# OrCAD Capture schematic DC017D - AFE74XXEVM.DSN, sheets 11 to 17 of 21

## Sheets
11 SHEET 09 - RX INPUTS: size B; title: AFE INPUTS
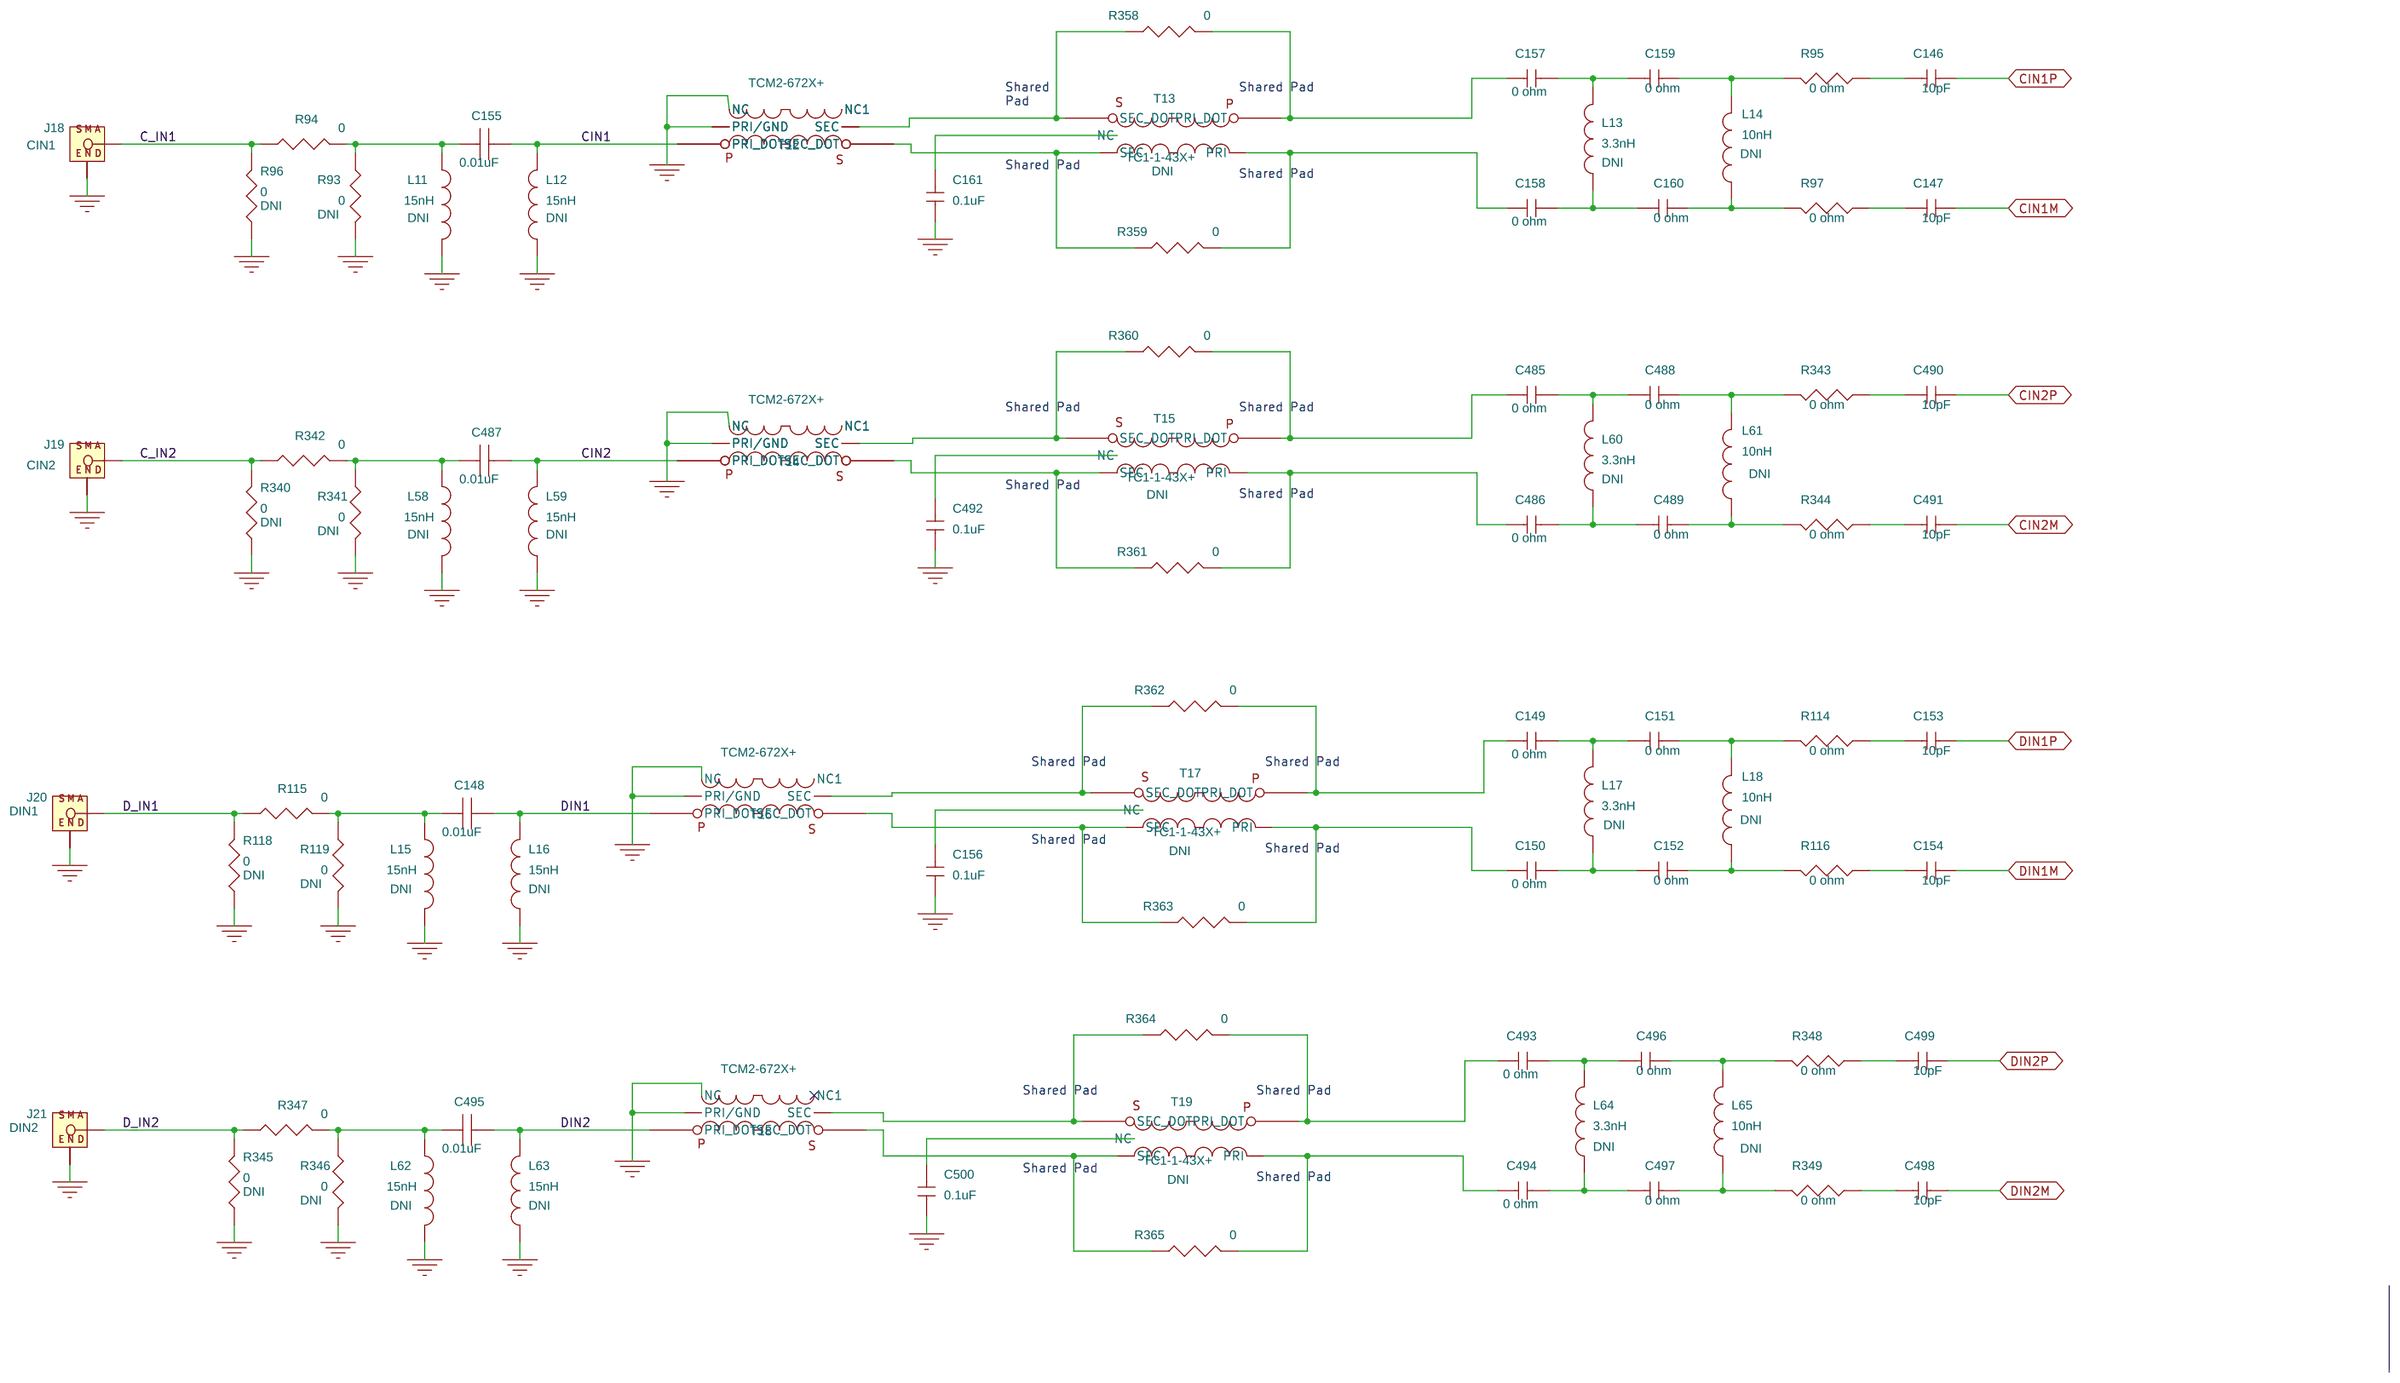
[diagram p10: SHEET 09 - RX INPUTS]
12 SHEET 10 - TX OUTPUTS: size B; title: AFE OUTPUTS
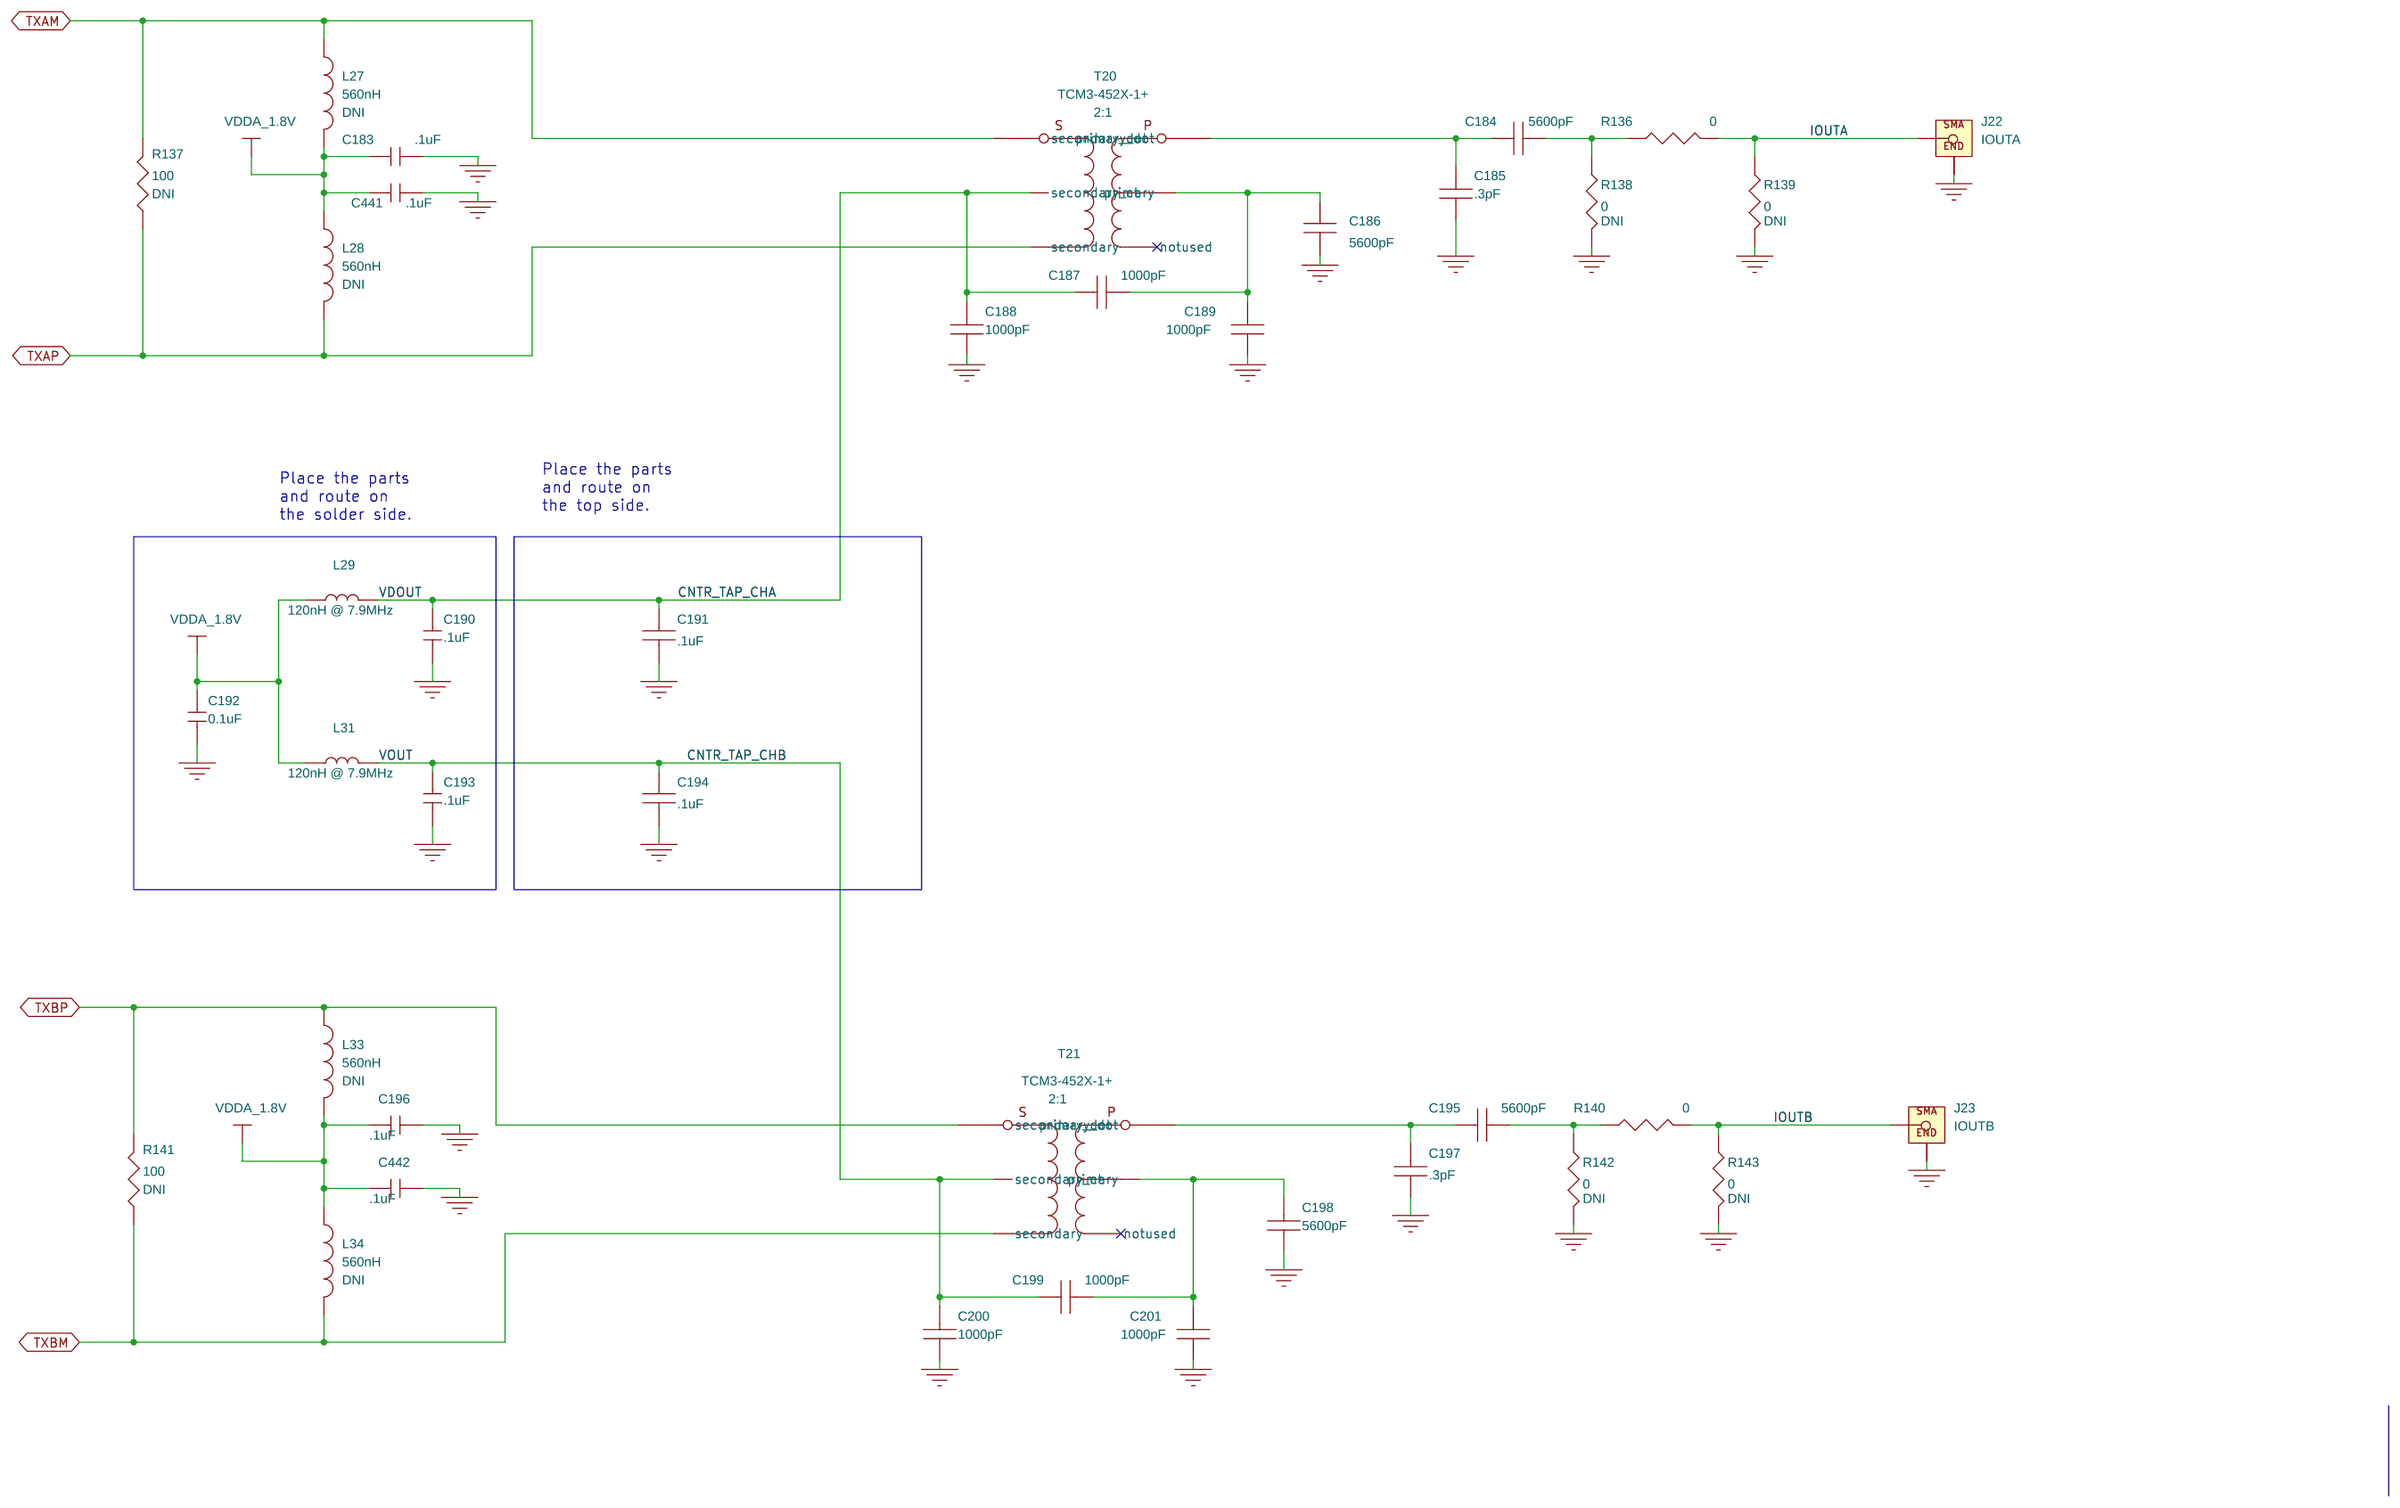
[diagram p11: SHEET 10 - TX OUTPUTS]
13 SHEET 11 - TX OUTPUTS: size B; title: AFE OUTPUTS
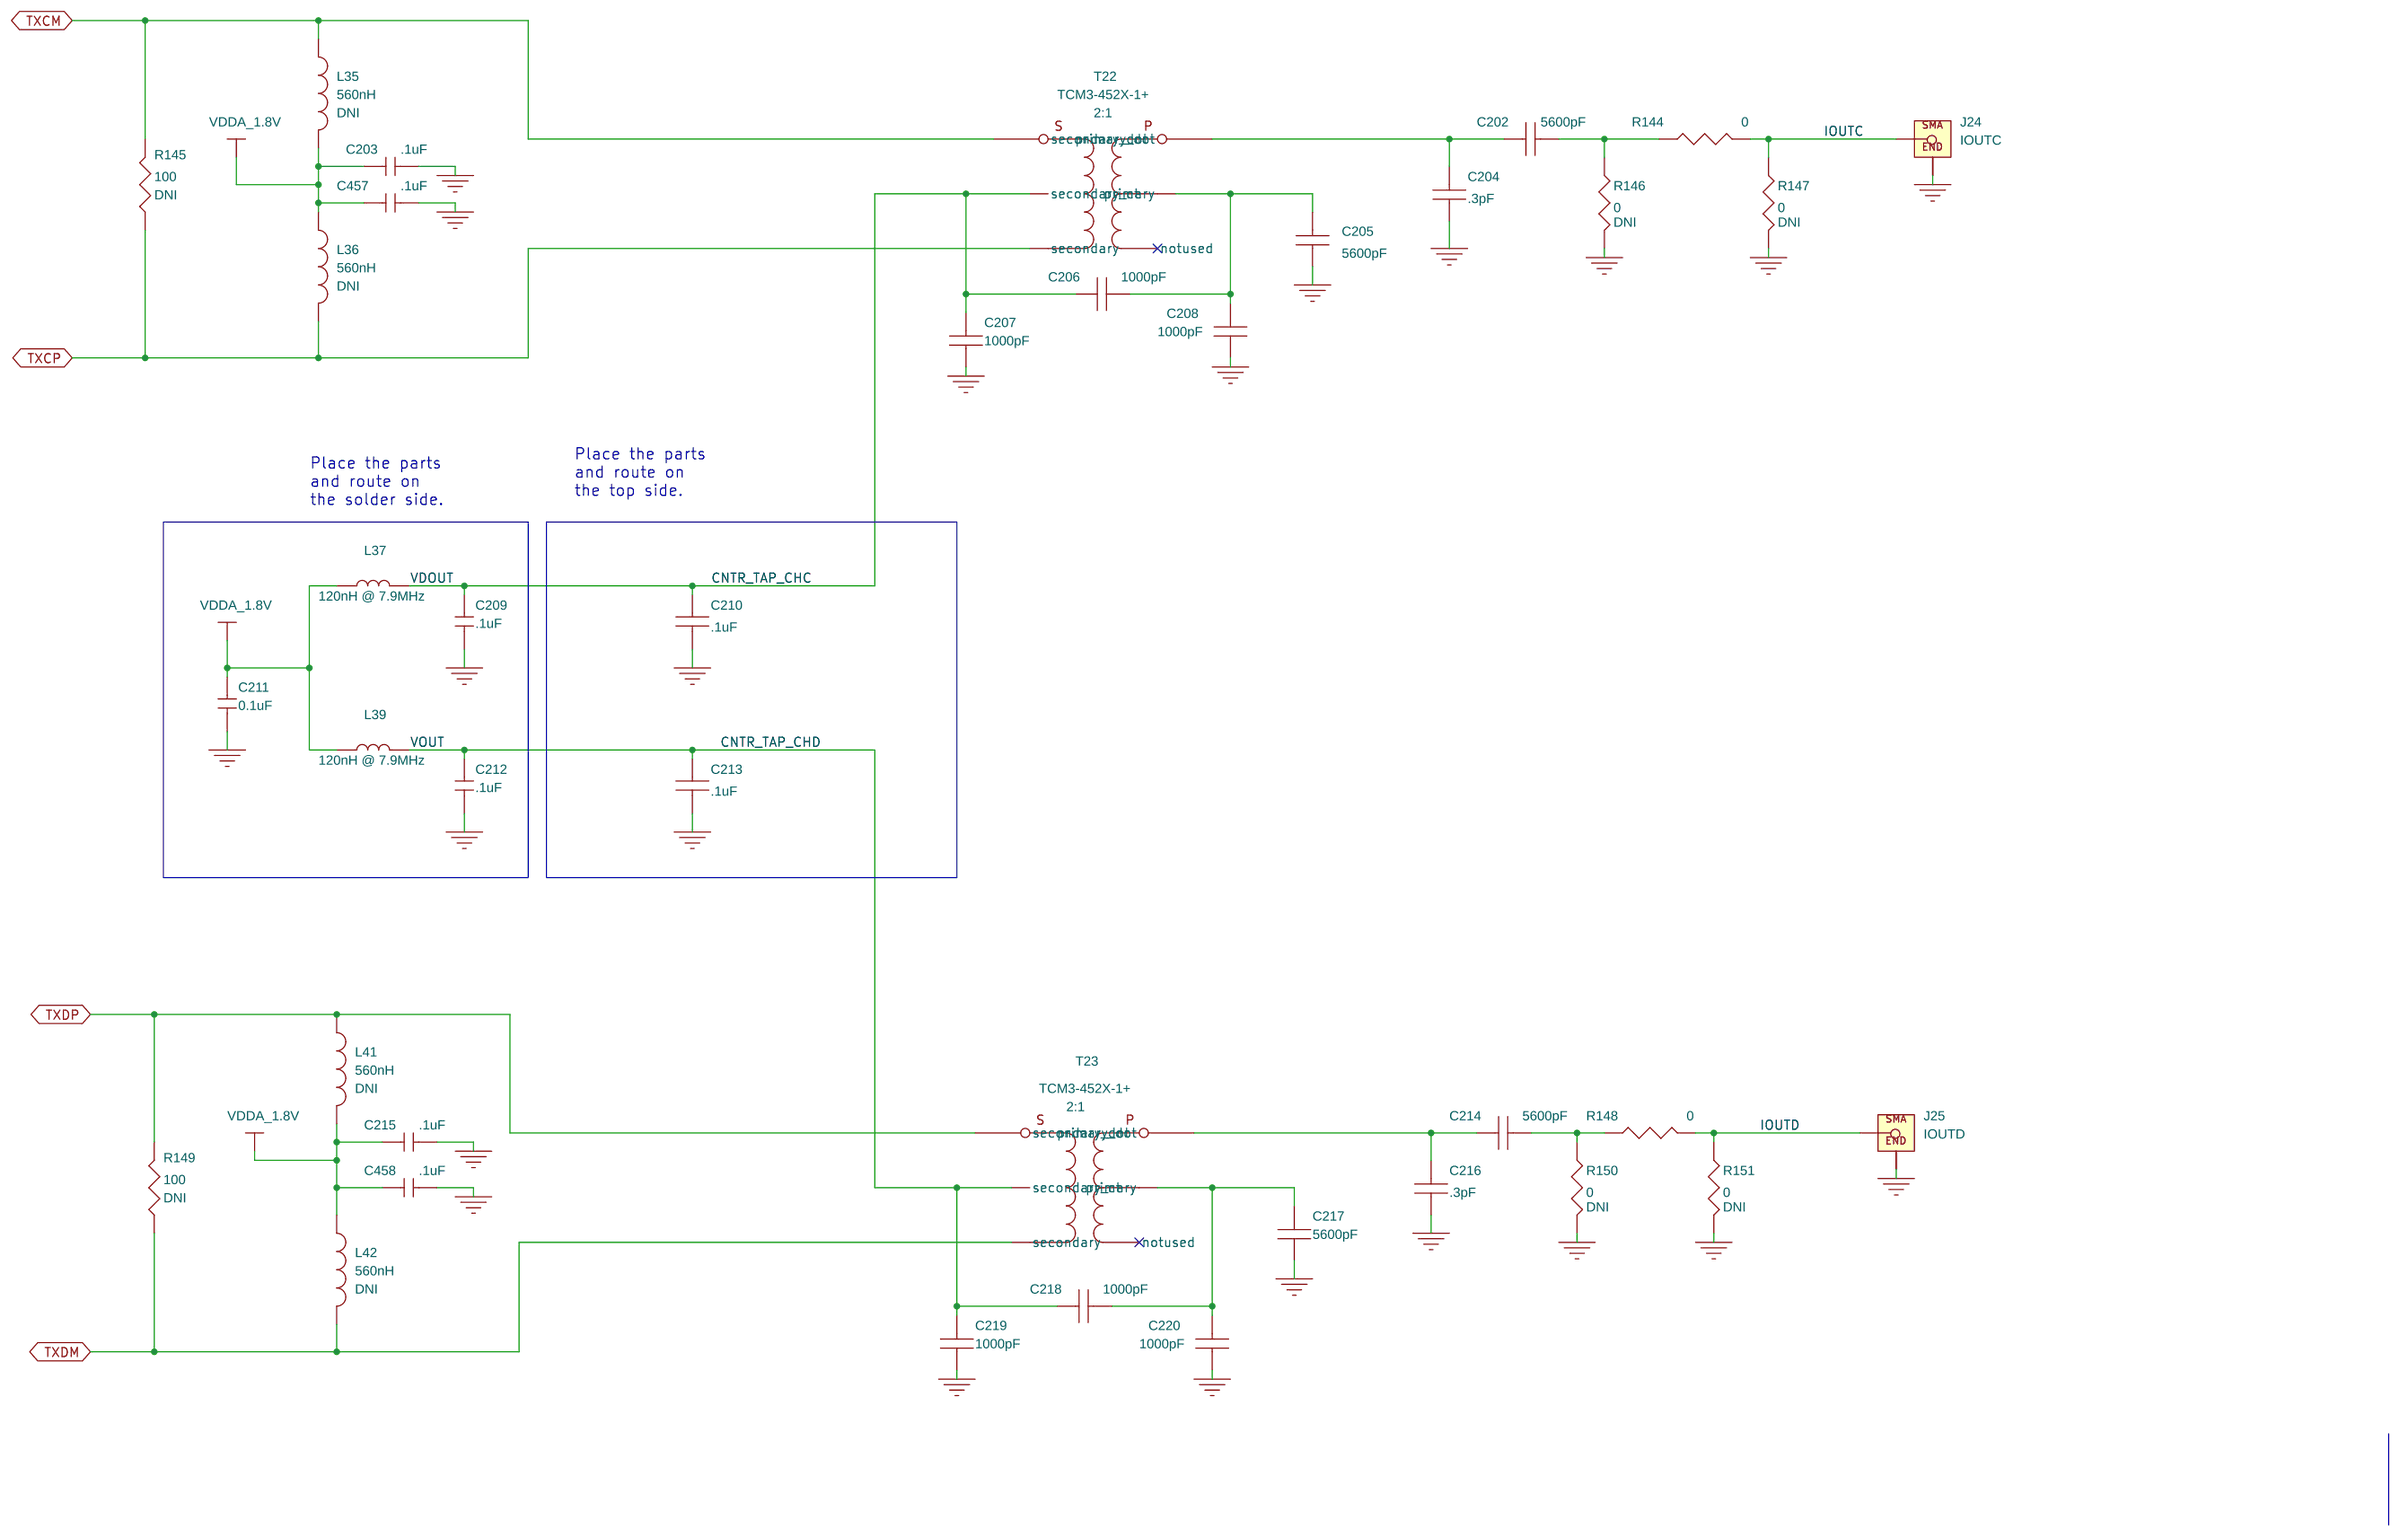
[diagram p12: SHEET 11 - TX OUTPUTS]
14 SHEET 12 - LMK INPUTS & OUTPUTS: size B; title: LMK
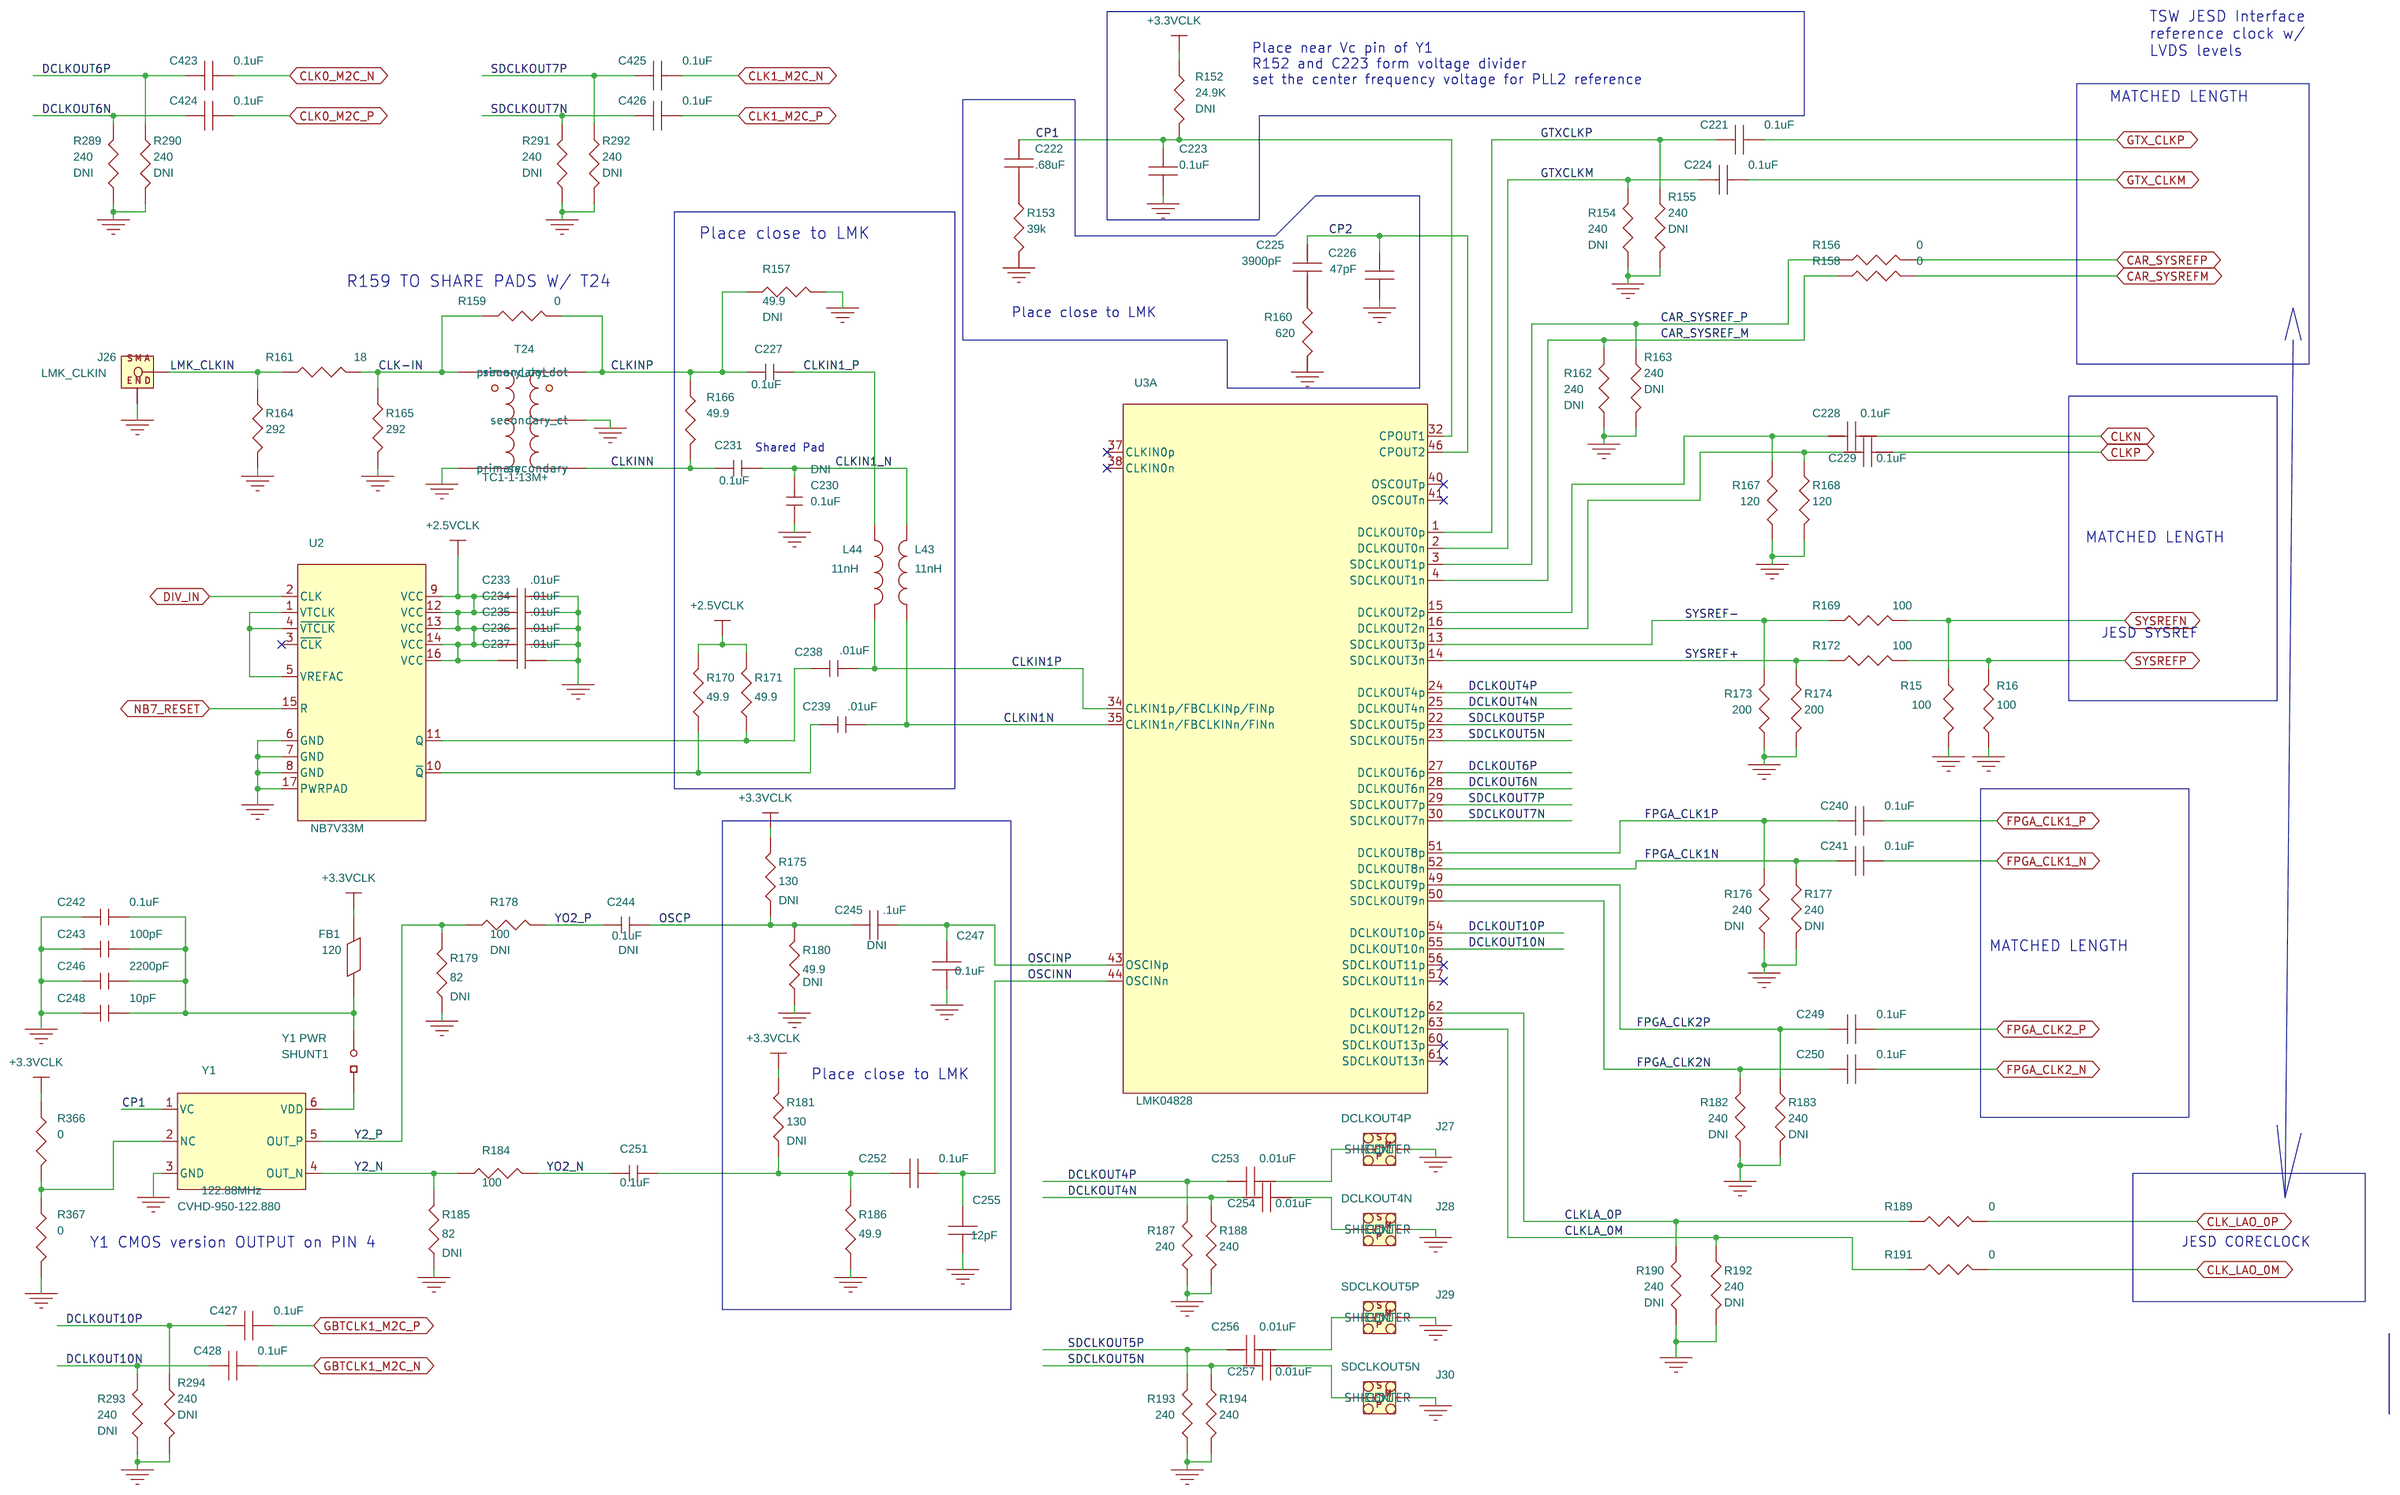
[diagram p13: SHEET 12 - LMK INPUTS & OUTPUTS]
15 SHEET 13 - LMK POWER & CONF: size B; title: LMK
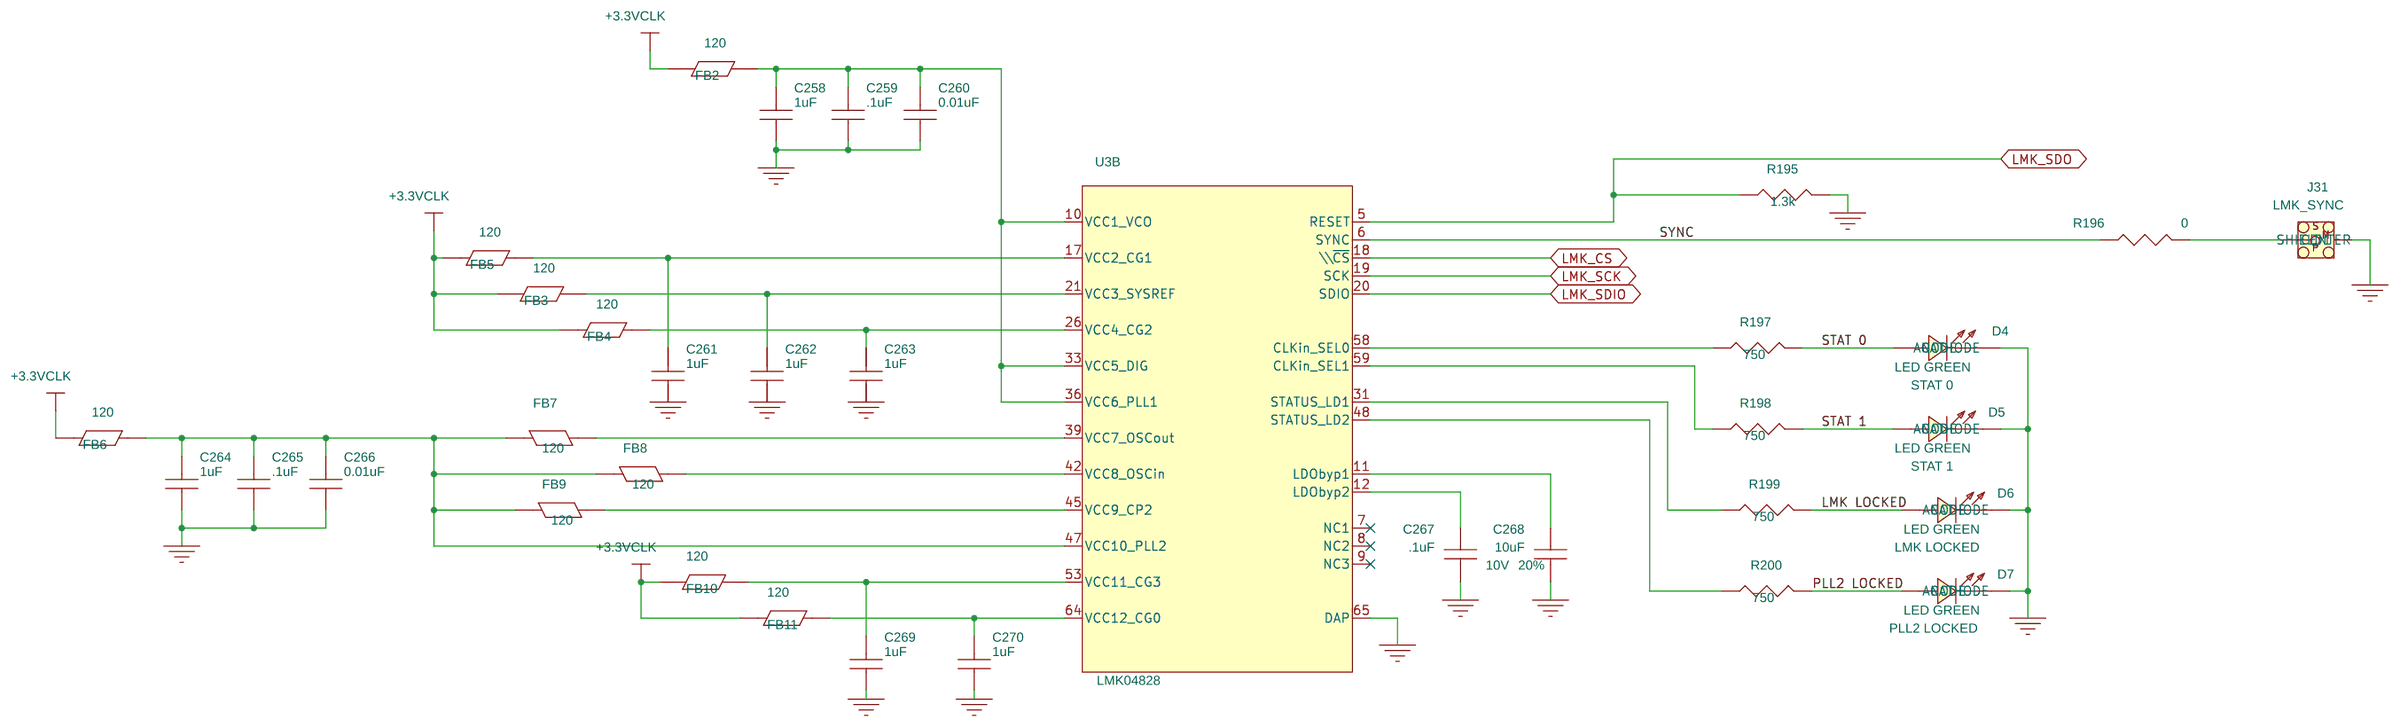
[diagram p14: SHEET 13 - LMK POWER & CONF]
16 SHEET 14 - FMC CONN: size B; title: FMC
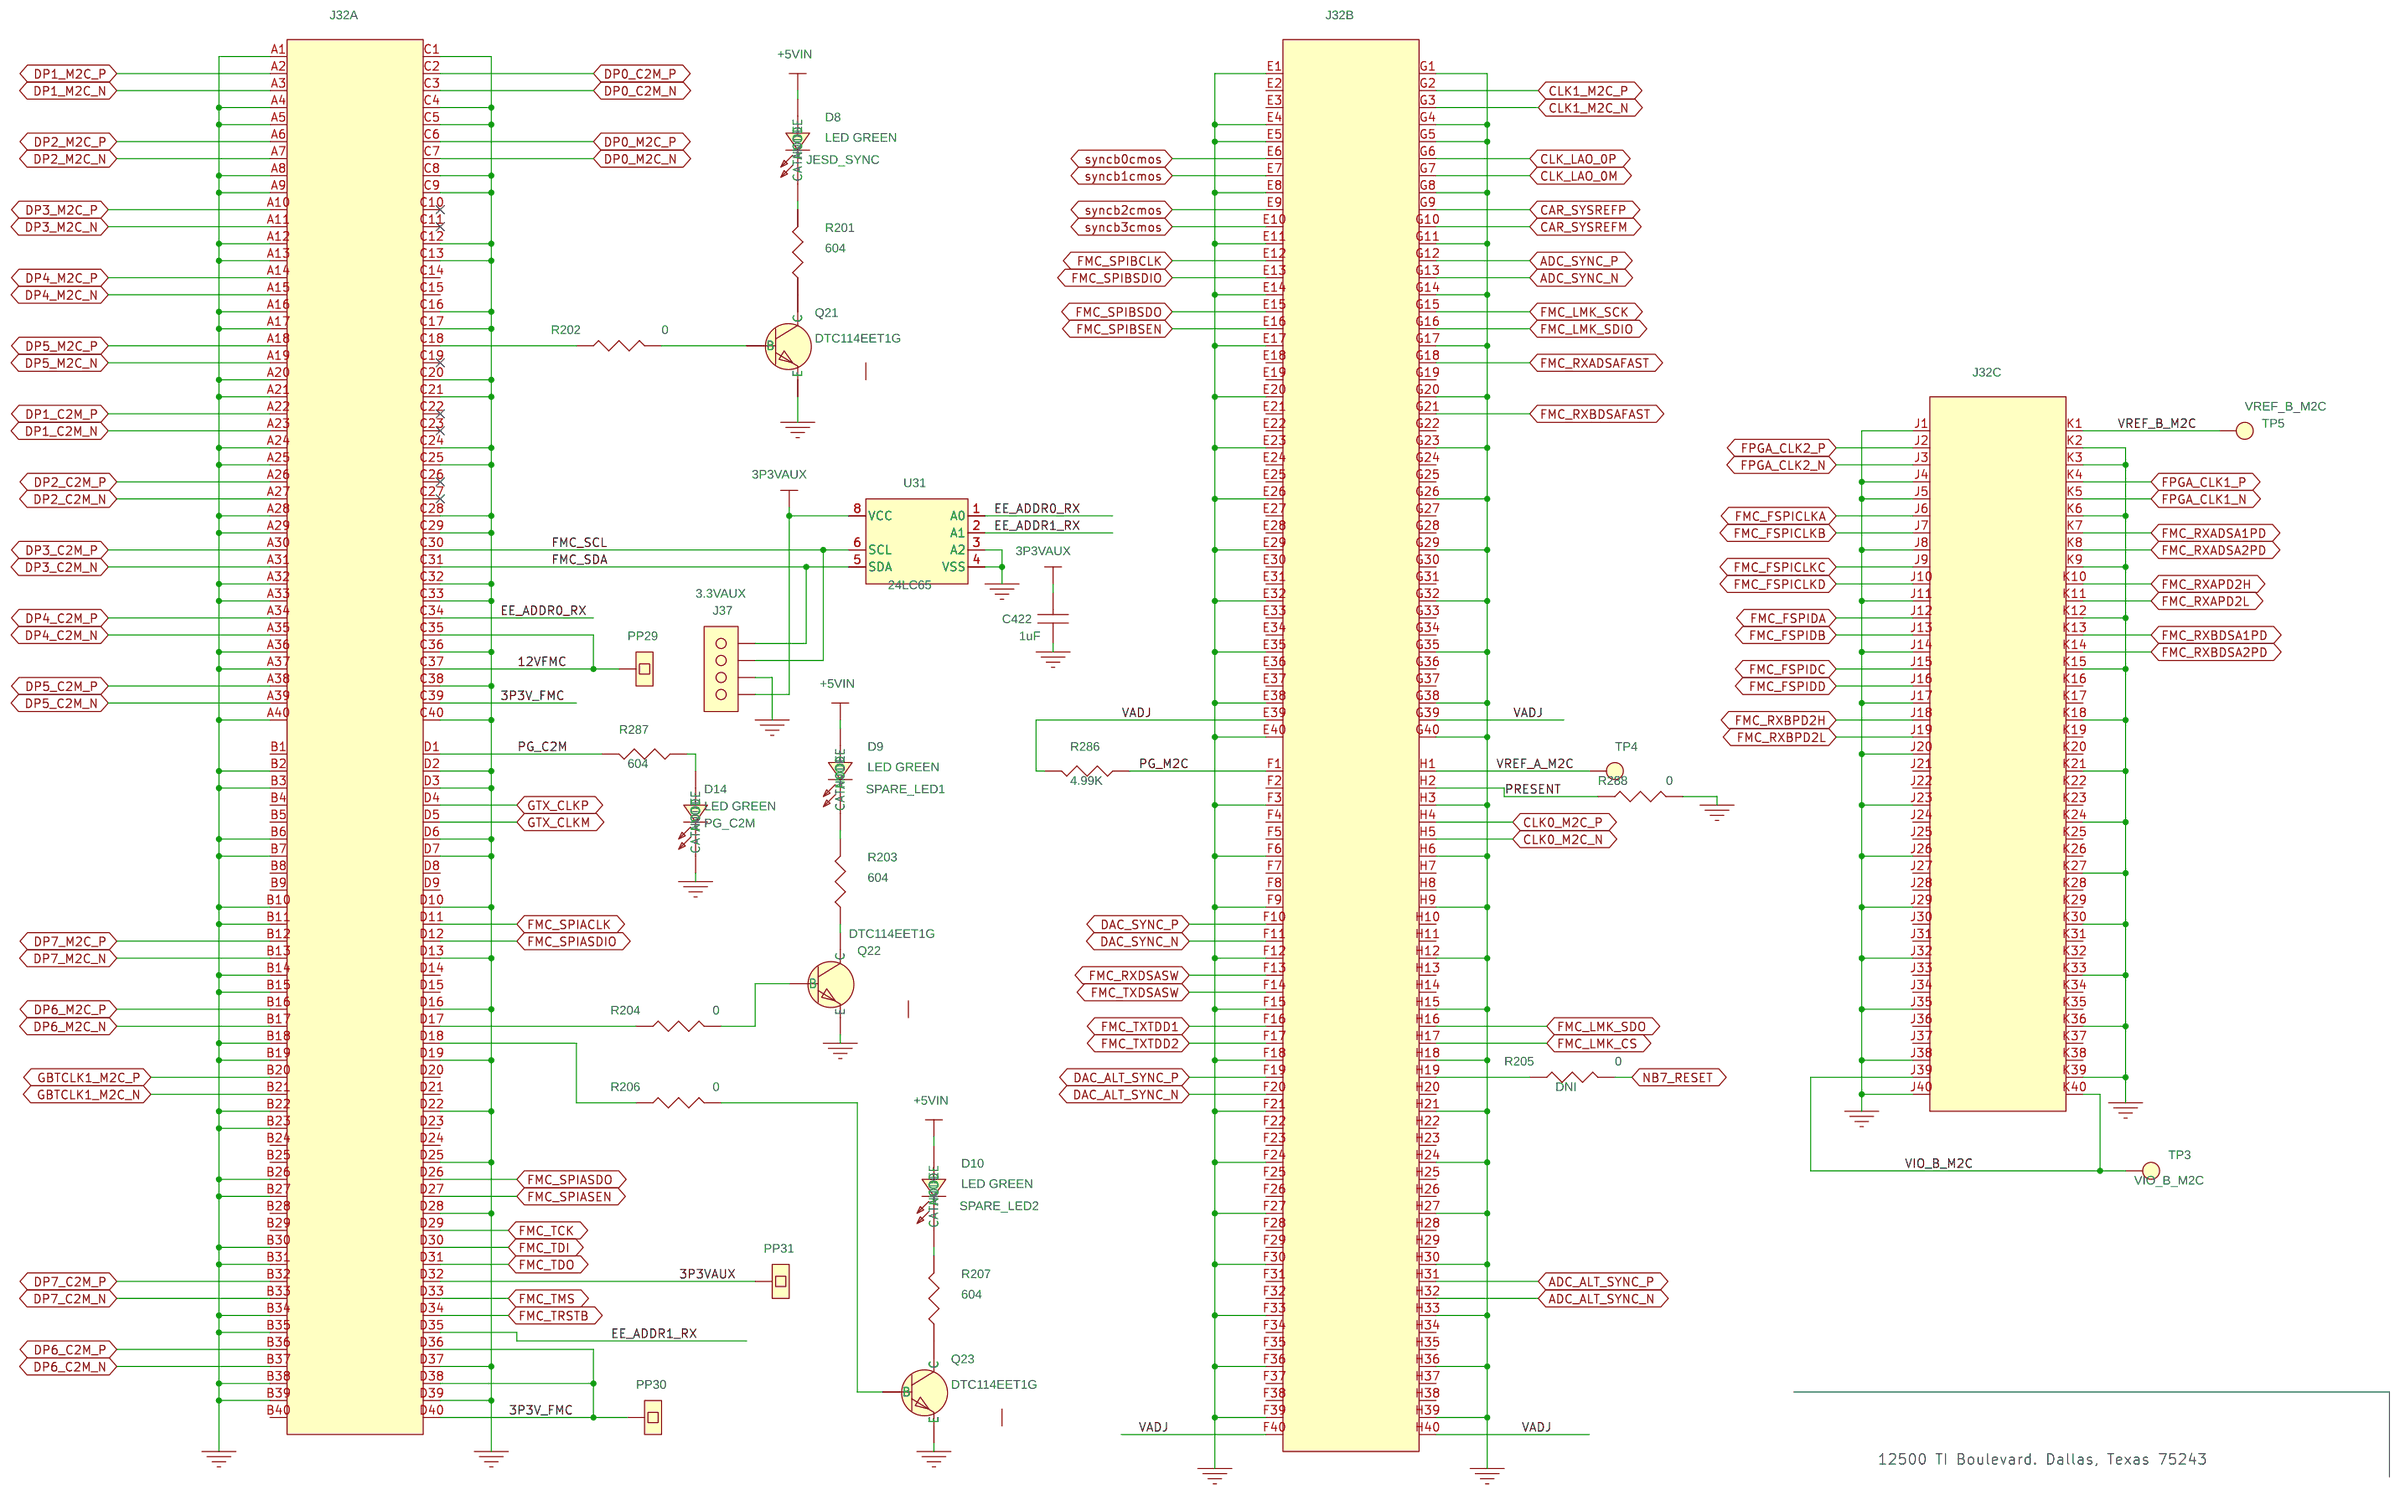
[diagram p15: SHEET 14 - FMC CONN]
17 SHEET 16 - POWER TREE: title: POWER TREE
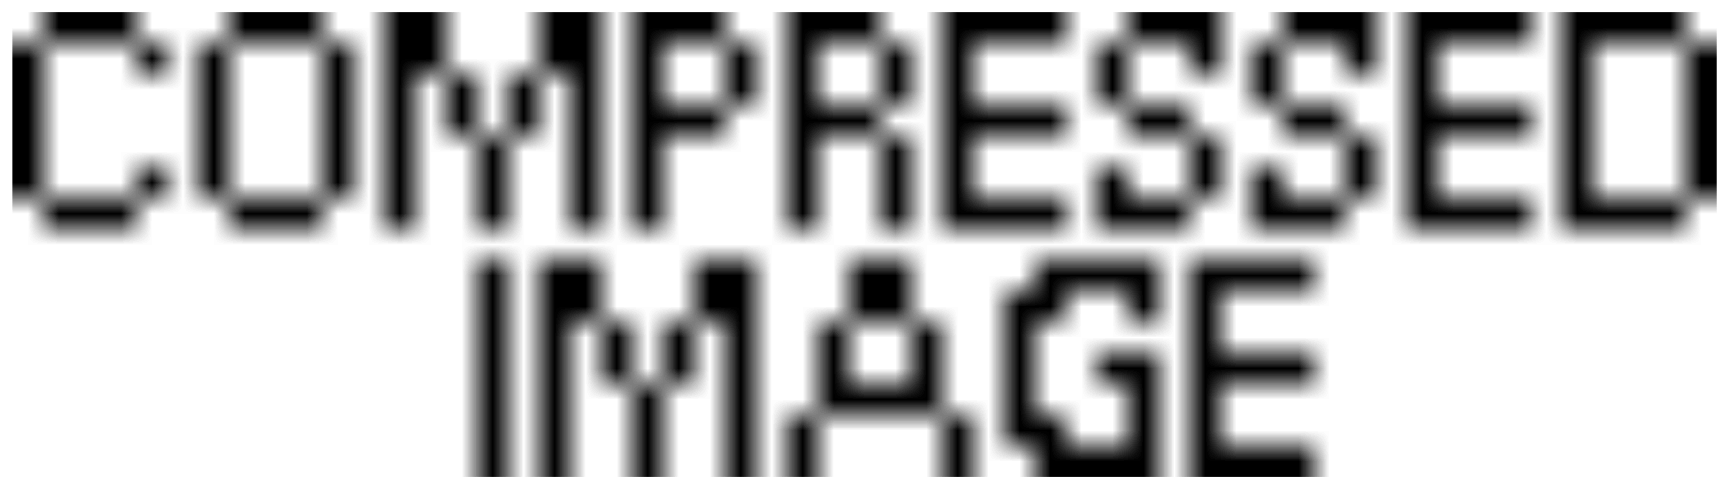
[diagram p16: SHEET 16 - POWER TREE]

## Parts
sheet SHEET 09 - RX INPUTS
C146  10pF  [0201]
C147  10pF  [0201]
C148  0.01uF  [0402]
C149  0 ohm  [0201]
C150  0 ohm  [0201]
C151  0 ohm  [0201]
C152  0 ohm  [0201]
C153  10pF  [0201]
C154  10pF  [0201]
C155  0.01uF  [0402]
C156  0.1uF  [0201]
C157  0 ohm  [0201]
C158  0 ohm  [0201]
C159  0 ohm  [0201]
C160  0 ohm  [0201]
C161  0.1uF  [0201]
C485  0 ohm  [0201]
C486  0 ohm  [0201]
C487  0.01uF  [0402]
C488  0 ohm  [0201]
C489  0 ohm  [0201]
C490  10pF  [0201]
C491  10pF  [0201]
C492  0.1uF  [0201]
C493  0 ohm  [0201]
C494  0 ohm  [0201]
C495  0.01uF  [0402]
C496  0 ohm  [0201]
C497  0 ohm  [0201]
C498  10pF  [0201]
C499  10pF  [0201]
C500  0.1uF  [0201]
J18  SMA, JACK, END LAUNCH  [SMA_SMEL_DUAL_PSF-S01_250x215]
J19  SMA, JACK, END LAUNCH  [SMA_SMEL_DUAL_PSF-S01_250x215]
J20  SMA, JACK, END LAUNCH  [SMA_SMEL_DUAL_PSF-S01_250x215]
J21  SMA, JACK, END LAUNCH  [SMA_SMEL_DUAL_PSF-S01_250x215]
L11  15nH  [0402]
L12  15nH  [0402]
L13  3.3nH  [0402]
L14  10nH  [0402]
L15  15nH  [0402]
L16  15nH  [0402]
L17  3.3nH  [0402]
L18  10nH  [0402]
L58  15nH  [0402]
L59  15nH  [0402]
L60  3.3nH  [0402]
L61  10nH  [0402]
L62  15nH  [0402]
L63  15nH  [0402]
L64  3.3nH  [0402]
L65  10nH  [0402]
R93  0  [0402]
R94  0  [0402]
R95  0 ohm  [0201]
R96  0  [0402]
R97  0 ohm  [0201]
R114  0 ohm  [0201]
R115  0  [0402]
R116  0 ohm  [0201]
R118  0  [0402]
R119  0  [0402]
R340  0  [0402]
R341  0  [0402]
R342  0  [0402]
R343  0 ohm  [0201]
R344  0 ohm  [0201]
R345  0  [0402]
R346  0  [0402]
R347  0  [0402]
R348  0 ohm  [0201]
R349  0 ohm  [0201]
R358  0  [0603]
R359  0  [0603]
R360  0  [0603]
R361  0  [0603]
R362  0  [0603]
R363  0  [0603]
R364  0  [0603]
R365  0  [0603]
T12  TCM2-672X+  [TFMR_6_160x150_50]
T13  TC1-1-43X+  [TFMR_5_150X150_50]
T14  TCM2-672X+  [TFMR_6_160x150_50]
T15  TC1-1-43X+  [TFMR_5_150X150_50]
T16  TCM2-672X+  [TFMR_6_160x150_50]
T17  TC1-1-43X+  [TFMR_5_150X150_50]
T18  TCM2-672X+  [TFMR_6_160x150_50]
T19  TC1-1-43X+  [TFMR_5_150X150_50]
sheet SHEET 10 - TX OUTPUTS
C183  .1uF  [0204]
C184  5600pF  [0402]
C185  .3pF  [0402]
C186  5600pF  [0402]
C187  1000pF  [0402]
C188  1000pF  [0402]
C189  1000pF  [0402]
C190  .1uF  [0402]
C191  .1uF  [0402]
C192  0.1uF  [0603]
C193  .1uF  [0402]
C194  .1uF  [0402]
C195  5600pF  [0402]
C196  .1uF  [0204]
C197  .3pF  [0402]
C198  5600pF  [0402]
C199  1000pF  [0402]
C200  1000pF  [0402]
C201  1000pF  [0402]
C441  .1uF  [0204]
C442  .1uF  [0204]
J22  SMA END LAUNCH  [SMA_SMEL_DUAL_PSF-S01_250x215]
J23  SMA END LAUNCH  [SMA_SMEL_DUAL_PSF-S01_250x215]
L27  560nH  [0402]
L28  560nH  [0402]
L29  120nH @ 7.9MHz  [IND_0603]
L31  120nH @ 7.9MHz  [IND_0603]
L33  560nH  [0402]
L34  560nH  [0402]
R136  0  [0402]
R137  100  [01005]
R138  0  [0402]
R139  0  [0402]
R140  0  [0402]
R141  100  [01005]
R142  0  [0402]
R143  0  [0402]
T20  TCM3-452X-1+  [TFMR_6_160x150_50]
T21  TCM3-452X-1+  [TFMR_6_160x150_50]
sheet SHEET 11 - TX OUTPUTS
C202  5600pF  [0402]
C203  .1uF  [0204]
C204  .3pF  [0402]
C205  5600pF  [0402]
C206  1000pF  [0402]
C207  1000pF  [0402]
C208  1000pF  [0402]
C209  .1uF  [0402]
C210  .1uF  [0402]
C211  0.1uF  [0603]
C212  .1uF  [0402]
C213  .1uF  [0402]
C214  5600pF  [0402]
C215  .1uF  [0204]
C216  .3pF  [0402]
C217  5600pF  [0402]
C218  1000pF  [0402]
C219  1000pF  [0402]
C220  1000pF  [0402]
C457  .1uF  [0204]
C458  .1uF  [0204]
J24  SMA END LAUNCH  [SMA_SMEL_DUAL_PSF-S01_250x215]
J25  SMA END LAUNCH  [SMA_SMEL_DUAL_PSF-S01_250x215]
L35  560nH  [0402]
L36  560nH  [0402]
L37  120nH @ 7.9MHz  [IND_0603]
L39  120nH @ 7.9MHz  [IND_0603]
L41  560nH  [0402]
L42  560nH  [0402]
R144  0  [0402]
R145  100  [01005]
R146  0  [0402]
R147  0  [0402]
R148  0  [0402]
R149  100  [01005]
R150  0  [0402]
R151  0  [0402]
T22  TCM3-452X-1+  [TFMR_6_160x150_50]
T23  TCM3-452X-1+  [TFMR_6_160x150_50]
sheet SHEET 12 - LMK INPUTS & OUTPUTS
C221  0.1uF  [0201]
C222  .68uF  [0402]
C223  0.1uF  [0201]
C224  0.1uF  [0201]
C225  3900pF  [0201]
C226  47pF  [0201]
C227  0.1uF  [0201]
C228  0.1uF  [0201]
C229  0.1uF  [0201]
C230  0.1uF  [0201]
C231  0.1uF  [0201]
C233  .01uF  [0201]
C234  .01uF  [0201]
C235  .01uF  [0201]
C236  .01uF  [0201]
C237  .01uF  [0201]
C238  .01uF  [0201]
C239  .01uF  [0201]
C240  0.1uF  [0201]
C241  0.1uF  [0201]
C242  0.1uF  [0201]
C243  100pF  [0201]
C244  0.1uF  [0201]
C245  .1uF  [0201]
C246  2200pF  [0201]
C247  0.1uF  [0201]
C248  10pF  [0201]
C249  0.1uF  [0201]
C250  0.1uF  [0201]
C251  0.1uF  [0201]
C252  0.1uF  [0201]
C253  0.01uF  [0201]
C254  0.01uF  [0201]
C255  12pF  [0201]
C256  0.01uF  [0201]
C257  0.01uF  [0201]
C423  0.1uF  [0201]
C424  0.1uF  [0201]
C425  0.1uF  [0201]
C426  0.1uF  [0201]
C427  0.1uF  [0201]
C428  0.1uF  [0201]
FB1  120  [0402]
J26  SMA, JACK, END LAUNCH  [SMA_SMEL_DUAL_PSF-S01_250x215]
J27  SMP CONN  [smp_b120]
J28  SMP CONN  [smp_b120]
J29  SMP CONN  [smp_b120]
J30  SMP CONN  [smp_b120]
L43  11nH  [0402]
L44  11nH  [0402]
R15  100  [0201]
R16  100  [0201]
R152  24.9K  [0201]
R153  39k  [0201]
R154  240  [0201]
R155  240  [0201]
R156  0  [0201]
R157  49.9  [0201]
R158  0  [0201]
R159  0  [0603]
R160  620  [0201]
R161  18  [0402]
R162  240  [0201]
R163  240  [0201]
R164  292  [0402]
R165  292  [0402]
R166  49.9  [0402]
R167  120  [0201]
R168  120  [0201]
R169  100  [0201]
R170  49.9  [0201]
R171  49.9  [0201]
R172  100  [0201]
R173  200  [0201]
R174  200  [0201]
R175  130  [0201]
R176  240  [0201]
R177  240  [0201]
R178  100  [0201]
R179  82  [0201]
R180  49.9  [0201]
R181  130  [0201]
R182  240  [0201]
R183  240  [0201]
R184  100  [0201]
R185  82  [0201]
R186  49.9  [0201]
R187  240  [0201]
R188  240  [0201]
R189  0  [0201]
R190  240  [0201]
R191  0  [0201]
R192  240  [0201]
R193  240  [0201]
R194  240  [0201]
R289  240  [0201]
R290  240  [0201]
R291  240  [0201]
R292  240  [0201]
R293  240  [0201]
R294  240  [0201]
R366  0  [0402]
R367  0  [0402]
SHUNT1  SHUNT JUMPER  [HDR_THVT_1x2_100_M]
T24  TC1-1-13M+  [TFMR_5_150x150_50]
U2  NB7V33M  [qfn_16_124x124_pwrpad]
Y1  122.88MHz  [VCXO_6_CUSTOM]
sheet SHEET 13 - LMK POWER & CONF
C258  1uF  [0402]
C259  .1uF  [0201]
C260  0.01uF  [0201]
C261  1uF  [0402]
C262  1uF  [0402]
C263  1uF  [0402]
C264  1uF  [0402]
C265  .1uF  [0201]
C266  0.01uF  [0201]
C267  .1uF  [0201]
C268  10uF  [0402]
C269  1uF  [0402]
C270  1uF  [0402]
D4  LED GREEN  [LED_0603]
D5  LED GREEN  [LED_0603]
D6  LED GREEN  [LED_0603]
D7  LED GREEN  [LED_0603]
FB2  120  [0402]
FB3  120  [0402]
FB4  120  [0402]
FB5  120  [0402]
FB6  120  [0402]
FB7  120  [0402]
FB8  120  [0402]
FB9  120  [0402]
FB10  120  [0402]
FB11  120  [0402]
J31  SMP CONN  [smp_b120]
R195  1.3k  [0201]
R196  0  [0402]
R197  750  [0402]
R198  750  [0402]
R199  750  [0402]
R200  750  [0402]
U3  LMK04828  [QFN_64_360X360_0P50MM_PWRPAD]  (sections A,B)
sheet SHEET 14 - FMC CONN
C422  1uF  [0402]
D8  LED GREEN  [LED_0603]
D9  LED GREEN  [LED_0603]
D10  LED GREEN  [LED_0603]
D14  LED GREEN  [LED_0603]
J32  CON_SMVT_40x10_SEAM  [CON_SMVT_40X10_SEAM_MTG]  (sections A,B,C)
J37  HDR, THVT, 4POS, .100, GOLD  [HDR_THVT_1x4_100_M]
PP29  PROBE POINT  [PROBE_POINT_22PAD]
PP30  PROBE POINT  [PROBE_POINT_22PAD]
PP31  PROBE POINT  [PROBE_POINT_22PAD]
Q21  DTC114EET1G  [SOT_416_3_63x31]
Q22  DTC114EET1G  [SOT_416_3_63x31]
Q23  DTC114EET1G  [SOT_416_3_63x31]
R201  604  [0402]
R202  0  [0402]
R203  604  [0402]
R204  0  [0402]
R205  0  [0402]
R206  0  [0402]
R207  604  [0402]
R286  4.99K  [0402]
R287  604  [0402]
R288  0  [0402]
TP3  TP_THVT_060_RND-WHT  [TP_THVT_060_RND]
TP4  TP_THVT_060_RND-WHT  [TP_THVT_060_RND]
TP5  TP_THVT_060_RND-WHT  [TP_THVT_060_RND]
U31  24LC65  [SO_8_210X212_50]

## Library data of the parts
C146 C147 C153 C154 C490 C491 C498 C499 = CAP_0603_0.1uF_H: Mfr_Name: Murata; Mfr_Part_Number: GJM0336C1E100GB01D; TOL: 2%; Voltage: 25V
C148 C155 C487 C495 = CAP_NP_1: Mfr_Name: MURATA; Mfr_Part_Number: GCM155R71H103KA55J; TOL: 10%; VOLTAGE: 50V
C149 C150 C157 C158 C485 C486 C493 C494 = CAP_0402_0.01uF_H: Mfr_Name: Panasonic; Mfr_Part_Number: ERJ-1GN0R00C
C151 C152 C159 C160 C488 C489 C496 C497 = CAP_0603_0.1uF_H: Mfr_Name: Panasonic; Mfr_Part_Number: ERJ-1GN0R00C
C156 C161 C227 C231 C492 C500 = CAP_0402_0.01uF_H: Mfr_Name: TDK; Mfr_Part_Number: C0603X7S1A104K030BC; TOL: 10%; VOLTAGE: 10V
J18 = SMA-END_PLUG_ROUND_0: Mfr_Name: Johnson Components; Mfr_Part_Number: 142-0711-821; TI_Silktext: CIN1
J19 = SMA-END_PLUG_ROUND_0: Mfr_Name: Johnson Components; Mfr_Part_Number: 142-0711-821; TI_Silktext: CIN2
J20 = SMA-END_PLUG_ROUND_0: Mfr_Name: Johnson Components; Mfr_Part_Number: 142-0711-821; TI_Silktext: DIN1
J21 = SMA-END_PLUG_ROUND_0: Mfr_Name: Johnson Components; Mfr_Part_Number: 142-0711-821; TI_Silktext: DIN2
L11 L12 L15 L16 L58 L59 L62 L63 = CHOKE: Mfr_Name: Coilcraft; Mfr_Part_Number: 0402HP-15NXGLU; Note: DNI
L13 L17 L60 L64 = CHOKE: Mfr_Name: Coilcraft; Mfr_Part_Number: 0402HP-3N3XGLU; Note: DNI
L14 L18 L61 L65 = CHOKE: Mfr_Name: Coilcraft; Mfr_Part_Number: 0402HP-10NXGLU; Note: DNI
R93 R96 R118 R119 R205 R340 R341 R345 R346 = Res_0603_Zero_H: Mfr_Part_Number: ERJ-2GE0R00X; Note: DNI
R94 R115 R202 R204 R206 R288 R342 R347 = Res_0603_Zero_H: Mfr_Part_Number: ERJ-2GE0R00X
R95 R97 R114 R116 R343 R344 R348 R349 = Res_0402_Zero_H_DNI: Mfr_Name: Panasonic; Mfr_Part_Number: ERJ-1GN0R00C
R159 R358-R365 = Res_0603_Zero_DNI: Mfr_Part_Number: ERJ-3GEY0R00V
T12 T14 T16 T18 = BALUN_TCM2-672X+: Mfr_Part_Number: TCM2-672X-1+
T13 T15 T17 T19 = BALUN_TC1-1-43X+: Mfr_Part_Number: TC1-1-43X-2+; Note: DNI
C183 C196 C203 C215 C441 C442 C457 C458 = CAP0402_0: Mfr_Name: Murata; Mfr_Part_Number: LLL153C80J104ME01E; TOL: 20%; Voltage: 6.3V
C184 C186 C195 C198 C202 C205 C214 C217 = CAPACITOR_NP_1: Mfr_Name: Yageo; Mfr_Part_Number: CC0402KRX7R7BB562; TOL: 10%; Voltage: 16V
C185 C197 C204 C216 = CAPACITOR_NP_1: Mfr_Name: MURATA; Mfr_Part_Number: GRM1555C1HR30WA01D; TOL: .05pF; Voltage: 50V
C187-C189 C199-C201 C206-C208 C218-C220 = CAPACITOR_NP_1: Mfr_Name: Samsung; Mfr_Part_Number: CL05B102KO5NNNC; TOL: 10%; Voltage: 16V
C190 C193 C209 C212 = CAP_0603_0.1uF: Mfr_Name: MURATA; Mfr_Part_Number: GCM155R71C104KA55D; Voltage: 16V
C191 C194 C210 C213 = CAPACITOR_NP_1: Mfr_Name: MURATA; Mfr_Part_Number: GCM155R71C104KA55D; TOL: 10%; Voltage: 16V
C192 C211 = CAP_0603_0.1uF
J22 = TMP_0: Mfr_Name: Johnson Components; Mfr_Part_Number: 142-0711-841; TI_Silktext: IOUTA
J23 = TMP_0: Mfr_Name: Johnson Components; Mfr_Part_Number: 142-0711-841; TI_Silktext: IOUTB
L27 L28 L33-L36 L41 L42 = CHOKE: Mfr_Name: Coilcraft; Mfr_Part_Number: 0402AF-561XJLU; Note: DNI
L29 L31 L37 L39 = IND_0603_120nH_H: Mfr_Name: COILCRAFT; Mfr_Part_Number: 0603AF-121XJRU
R136 R140 R144 R148 = Res_0402_10_H: Mfr_Part_Number: ERJ-2GE0R00X
R137 R141 R145 R149 = Res_0402_100_H: Mfr_Part_Number: ERJ-XGNJ101Y; Note: DNI
R138 R139 R142 R143 R146 R147 R150 R151 = R: Mfr_Name: PANASONIC; Mfr_Part_Number: ERJ-2GE0R00X; Note: DNI; TOL: 5%
T20-T23 = TFMR_6_TCM3-452X+: Impedance Ratio: 2:1; Mfr_Part_Number: TCM2-452X-2+
J24 = TMP_0: Mfr_Name: Johnson Components; Mfr_Part_Number: 142-0711-841; TI_Silktext: IOUTC
J25 = TMP_0: Mfr_Name: Johnson Components; Mfr_Part_Number: 142-0711-841; TI_Silktext: IOUTD
C221 C224 C240 C241 C247 C249 C250 C423-C428 = CAPACITOR_NP_1: Mfr_Name: MURATA; Mfr_Part_Number: GRM033R61A104KE15D; TOL: 10%; Voltage: 16V
C222 = CAP_NP_0: Mfr_Name: TDK; Mfr_Part_Number: C1005X7S0J684K050BC; TOL: 10%; VOLTAGE: 6.3V
C223 C252 = CAP_NP_0: Mfr_Name: MURATA; Mfr_Part_Number: GRM033R61A104KE15D; TOL: 10%; VOLTAGE: 16V
C225 = CAP_NP_0: Mfr_Name: AVX; Mfr_Part_Number: 0201ZD392KAT2A; TOL: 10%; VOLTAGE: 10V
C226 = CAP_NP_0: Mfr_Name: MURATA; Mfr_Part_Number: GRM0335C1E470JA01D; TOL: 5%; VOLTAGE: 25V
C228 C229 = CAP_NP_1: Mfr_Name: MURATA; Mfr_Part_Number: GRM033R61A104KE15D; TOL: 10%; VOLTAGE: 16V
C230 = CAP_0402_0.1uF: Mfr_Name: MURATA; Mfr_Part_Number: GRM033R61A104KE15D; Note: DNI; TOL: 10%; VOLTAGE: 16V
C233-C239 = CAP_0402_0.01uF_H: Mfr_Part_Number: GRM033R71A103KA01D; TOL: 10%; VOLTAGE: 10V
C242 C251 = CAP_0402_0.1uF_H: Mfr_Part_Number: GRM033R61A104KE15D; TOL: 10%; Voltage: 16V
C243 = CAP_0603_100pF_H: Mfr_Name: Murata; Mfr_Part_Number: GRM033R71E101KA01D
C244 = CAP_0402_0.1uF_H: Mfr_Part_Number: GRM033R61A104KE15D; Note: DNI; TOL: 10%; Voltage: 16V
C245 = CAP_NP_0: Mfr_Name: MURATA; Mfr_Part_Number: GRM033R61A104KE15D; Note: DNI; TOL: 10%; VOLTAGE: 16V
C246 = CAP_0402_2200pF_H: Mfr_Part_Number: GRM033R71C222KA88D
C248 = CAP_0402_10pF_H: Mfr_Part_Number: GJM0336C1E100GB01D
C253 C254 C256 C257 = CAP_NP_1: Mfr_Name: MURATA; Mfr_Part_Number: GRM033R71A103KA01D; TOL: 10%; VOLTAGE: 10V
C255 = CAPACITOR_NP_1: Mfr_Name: Kemet; Mfr_Part_Number: CBR02C120F3GAC; TOL: 1%; Voltage: 25V
FB1-FB11 = FERRITE_BEAD_0402_H: Isat: 500mA; Mfr_Name: Taiyo Yuden; Mfr_Part_Number: BKP1005HS121-T
J26 = SMA-END_PLUG_ROUND_0: Mfr_Name: Johnson Components; Mfr_Part_Number: 142-0711-821; TI_Silktext: LMK_CLKIN
J27 = SMP_PLUG_SMT: TI_Silktext: DCLKOUT4P
J28 = SMP_PLUG_SMT: TI_Silktext: DCLKOUT4N
J29 = SMP_PLUG_SMT: TI_Silktext: SDCLKOUT5P
J30 = SMP_PLUG_SMT: TI_Silktext: SDCLKOUT5N
L43 L44 = CHOKE: Mfr_Name: Coilcraft; Mfr_Part_Number: 0402HP-11NXGLU
R15 R16 R169 R172 = Res_0402_Zero_H_DNI: Mfr_Part_Number: ERJ-1GNJ101C
R152 = Res_0402_24.9: Mfr_Part_Number: ERJ-1GNF2492C; Note: DNI
R153 = R_1: CLASS: DISCRETE; Mfr_Name: PANASONIC; Mfr_Part_Number: ERJ-1GNF3902C; TOL: 1%
R154 R155 R162 R163 R176 R177 R182 R183 R190 R192 R289-R294 = Res_0402_249: Mfr_Part_Number: ERJ-U01F2400C; Note: DNI
R156 R158 R189 R191 = Res_0402_Zero_H_DNI: Mfr_Part_Number: ERJ-1GN0R00C
R157 = Res_0402_49.9: Mfr_Name: VISHAY DALE; Mfr_Part_Number: CRCW020149R9FKED; Note: DNI; TOL: 1%; Wattage: 1/20W
R160 = R_1: CLASS: DISCRETE; Mfr_Name: PANASONIC; Mfr_Part_Number: ERJ-1GNJ621C; TOL: 1%
R161 = Res_0402_18: Mfr_Part_Number: ERJ-2RKF18R0X
R164 R165 = Res_0402_270: Mfr_Part_Number: ERJ-2RKF2940X
R166 = Res_0402_49.9: Mfr_Part_Number: ERJ-2RKF49R9X
R167 R168 = Res_0402_249: Mfr_Part_Number: ERJ-1GNJ121C
R170 R171 R186 = RESISTOR_0: CLASS: DISCRETE; Mfr_Name: VISHAY DALE; Mfr_Part_Number: CRCW020149R9FKED; TOL: 1%; Wattage: 1/20W
R173 R174 = Res_0402_249: Mfr_Part_Number: ERJ-1GNF2000C
R175 R181 = RESISTOR_0: CLASS: DISCRETE; Mfr_Name: PANASONIC; Mfr_Part_Number: ERJ-1GNF1300C; Note: DNI; TOL: 1%; Wattage: 1/20W
R178 = Res_0402_100_H: Mfr_Part_Number: ERJ-1GNJ101C; Note: DNI
R179 R185 = RESISTOR_0: CLASS: DISCRETE; Mfr_Name: Panasonic; Mfr_Part_Number: ERJ-1GNF82R0C; Note: DNI; TOL: 1%; Wattage: 1/20W
R180 = RESISTOR_0: CLASS: DISCRETE; Mfr_Name: VISHAY DALE; Mfr_Part_Number: CRCW020149R9FKED; Note: DNI; TOL: 1%; Wattage: 1/20W
R184 = Res_0402_100_H: Mfr_Part_Number: ERJ-1GNJ101C
R187 R188 R193 R194 = Res_0402_249: Mfr_Part_Number: ERJ-U01F2400C
R366 R367 = Res_0402_Zero_DNI: Mfr_Part_Number: ERJ-2GE0R00X
SHUNT1 = HDR_2x1_0: Mfr_Part_Number: JL-100-25-T; TI_Silktext: Y1 PWR
T24 = TFMR_5_TC1-1-13MA+: Mfr-_Part_Number: TC1-1-13MA+; Mfr_Part_Number: TC1-1-13M-23+
U2 = NB7V33M: Mfr_Name: On Semi; Mfr_Part_Number: NB7V33MMNG
Y1 = OSC_SM_6_TCO-2100-SERIES_2: Mfr_Name: Crystek; Mfr_Part_Number: CVHD-950-122.880
C258 C261-C264 C269 C270 = CAPACITOR_NP_1: Mfr_Name: Murata; Mfr_Part_Number: GRM153R61A105ME95D; TOL: 10%; Voltage: 10V
C259 C265 C267 = CAPACITOR_NP_1: Mfr_Name: MURATA; Mfr_Part_Number: GRM033R61A104KE15D; TOL: 10%; Voltage: 10V
C260 C266 = CAPACITOR_NP_1: Mfr_Name: MURATA; Mfr_Part_Number: GRM033R71A103KA01D; TOL: 10%; Voltage: 10V
C268 = CAP_NP_2: CLASS: DISCRETE; Mfr_Name: Samsung; Mfr_Part_Number: CL05A106MP5NUNC; TOL: 20%; VOLTAGE: 10V
D4 = LED: Mfr_Name: LITE ON; Mfr_Part_Number: LTST-S270KGKT; TI_Silktext: STAT 0
D5 = LED: Mfr_Name: LITE ON; Mfr_Part_Number: LTST-S270KGKT; TI_Silktext: STAT 1
D6 = LED: Mfr_Name: LITE ON; Mfr_Part_Number: LTST-S270KGKT; TI_Silktext: LMK LOCKED
D7 = LED: Mfr_Name: LITE ON; Mfr_Part_Number: LTST-S270KGKT; TI_Silktext: PLL2 LOCKED
J31 = SMP_PLUG_SMT: TI_Silktext: LMK_SYNC
R195 = RESISTOR_0: CLASS: DISCRETE; Mfr_Name: PANASONIC; Mfr_Part_Number: ERJ-1GNF1301C
R196 = R: Mfr_Name: PANASONIC; Mfr_Part_Number: ERJ-2GE0R00X; TOL: 5%
R197-R200 = RESISTOR_0: CLASS: DISCRETE; Mfr_Name: Panasonic; Mfr_Part_Number: ERJ-2RKF7500X
U3 = LMK04828: Mfr_Name: Texas Instruments; Mfr_Part_Number: LMK04828BISQ/NOPB
C422 = CAP_NP_1: Mfr_Name: Murata; Mfr_Part_Number: GRM153R61A105ME95D; TOL: 10%; VOLTAGE: 10V
D8 = LED: CLASS: DISCRETE; Mfr_Name: PANASONIC; Mfr_Part_Number: LNJ337W83RA; TI_SILKTEXT: JESD_SYNC
D9 = LED: CLASS: DISCRETE; Mfr_Name: PANASONIC; Mfr_Part_Number: LNJ337W83RA; TI_SILKTEXT: SPARE_LED1
D10 = LED: CLASS: DISCRETE; Mfr_Name: PANASONIC; Mfr_Part_Number: LNJ337W83RA; TI_SILKTEXT: SPARE_LED2
D14 = LED: CLASS: DISCRETE; Mfr_Name: PANASONIC; Mfr_Part_Number: LNJ337W83RA; TI_SILKTEXT: PG_C2M
J32 = CON_SMVT_40X10_ASP-134487-01: Mfr_Part_Number: SEAM-40-02.0-S-10-2-A-K-TR
J37 = HEADER_1x4_100: TI_SILKTEXT: 3.3VAUX
PP29 = PROBE_POINT_0: Mfr_Name: Harwin; Mfr_Part_Number: P1113SS3; Note: DNI; TI_Silktext: 12VFMC
PP30 PP31 = PROBE_POINT_0: Mfr_Name: Harwin; Mfr_Part_Number: P1113SS3; Note: DNI; TI_Silktext: 3P3V_FMC
Q21-Q23 = MMBT2222A: Mfr_Name: ON Semiconductor
R201 R203 R207 R287 = R: Mfr_Name: PANASONIC; Mfr_Part_Number: ERJ-2RKF6040X; TOL: 1%; VOLTAGE: 1/10W
R286 = R: Mfr_Name: PANASONIC; Mfr_Part_Number: ERJ-2RKF4991X; TOL: 1%; VOLTAGE: 1/10W
TP3 = TP_THVT_060_RND-WHT: Mfr_Name: Keystone; Mfr_Part_Number: 5007; TI_SILKTEXT: VIO_B_M2C
TP4 = TP_THVT_060_RND-WHT: Mfr_Name: Keystone; Mfr_Part_Number: 5007; TI_SILKTEXT: VREF_A_M2C
TP5 = TP_THVT_060_RND-WHT: Mfr_Name: Keystone; Mfr_Part_Number: 5007; TI_SILKTEXT: VREF_B_M2C
U31 = 24LC65: Mfr_Name: MICROCHIP TECHNOLOGY; Mfr_Part_Number: 24LC65T-I/SM

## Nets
12VFMC: J32.C35 J32.C37 PP29.1
+2.5VCLK: C233.1 C234.1 C235.1 C236.1 C237.1 R170.1 R171.1 U2.9(VCC) U2.12(VCC) U2.13(VCC) U2.14(VCC) U2.16(VCC) ; also on sheet 18
+3.3VCLK: FB1.2 FB2.1 FB3.1 FB4.1 FB5.1 FB6.1 FB10.1 FB11.1 R152.1 R175.1 R181.1 R366.1 ; also on sheet 18
+5VIN: D8.1(ANODE) D9.1(ANODE) D10.1(ANODE) ; also on sheet 1 2 6 18 19 20 21
GND: C156.1 C161.1 C183.2 C185.1 C186.2 C188.1 C189.1 C190.2 C191.2 C192.2 C193.2 C194.2 C196.2 C197.1 C198.1 C200.1 C201.1 C203.2 C204.1 C205.1 C207.1 C208.1 C209.2 C210.2 C211.2 C212.2 C213.2 C215.2 C216.1 C217.1 C219.1 C220.1 C223.2 C226.2 C230.1 C233.2 C234.2 C235.2 C236.2 C237.2 C242.1 C243.1 C246.1 C247.1 C248.1 C255.1 C258.1 C259.1 C260.1 C261.1 C262.1 C263.1 C264.1 C265.1 C266.1 C267.2 C268.2 C269.1 C270.1 C422.1 C441.2 C442.2 C457.2 C458.2 C492.1 C500.1 D4.2(CATHODE) D5.2(CATHODE) D6.2(CATHODE) D7.2(CATHODE) D14.2(CATHODE) J18.2(SHIELD3) J18.3(SHIELD4) J18.4(SHIELD1) J18.5(SHIELD2) J19.2(SHIELD3) J19.3(SHIELD4) J19.4(SHIELD1) J19.5(SHIELD2) J20.2(SHIELD3) J20.3(SHIELD4) J20.4(SHIELD1) J20.5(SHIELD2) J21.2(SHIELD3) J21.3(SHIELD4) J21.4(SHIELD1) J21.5(SHIELD2) J22.2(GND) J22.3(GND) J22.4(GND) J22.5(GND) J23.2(GND) J23.3(GND) J23.4(GND) J23.5(GND) J24.2(GND) J24.3(GND) J24.4(GND) J24.5(GND) J25.2(GND) J25.3(GND) J25.4(GND) J25.5(GND) J26.2(SHIELD3) J26.3(SHIELD4) J26.4(SHIELD1) J26.5(SHIELD2) J27.2(SHIELD1) J28.2(SHIELD1) J29.2(SHIELD1) J30.2(SHIELD1) J31.2(SHIELD1) J32.A1 J32.A4 J32.A5 J32.A8 J32.A9 J32.A12 J32.A13 J32.A16 J32.A17 J32.A20 J32.A21 J32.A24 J32.A25 J32.A28 J32.A29 J32.A32 J32.A33 J32.A36 J32.A37 J32.A40 J32.B2 J32.B3 J32.B6 J32.B7 J32.B10 J32.B11 J32.B14 J32.B15 J32.B18 J32.B19 J32.B22 J32.B23 J32.B26 J32.B27 J32.B30 J32.B31 J32.B34 J32.B35 J32.B38 J32.B39 J32.C1 J32.C4 J32.C5 J32.C8 J32.C9 J32.C12 J32.C13 J32.C16 J32.C17 J32.C20 J32.C21 J32.C24 J32.C25 J32.C28 J32.C29 J32.C32 J32.C33 J32.C36 J32.C38 J32.C40 J32.D2 J32.D3 J32.D6 J32.D7 J32.D10 J32.D13 J32.D16 J32.D19 J32.D22 J32.D25 J32.D28 J32.D37 J32.D39 J32.E1 J32.E4 J32.E5 J32.E8 J32.E11 J32.E14 J32.E17 J32.E20 J32.E23 J32.E26 J32.E29 J32.E32 J32.E35 J32.E38 J32.E40 J32.F3 J32.F6 J32.F9 J32.F12 J32.F15 J32.F18 J32.F21 J32.F24 J32.F27 J32.F30 J32.F33 J32.F36 J32.F39 J32.G1 J32.G4 J32.G5 J32.G8 J32.G11 J32.G14 J32.G17 J32.G20 J32.G23 J32.G26 J32.G29 J32.G32 J32.G35 J32.G38 J32.G40 J32.H3 J32.H6 J32.H9 J32.H12 J32.H15 J32.H18 J32.H21 J32.H24 J32.H27 J32.H30 J32.H33 J32.H36 J32.H39 J32.J1 J32.J4 J32.J5 J32.J8 J32.J11 J32.J14 J32.J17 J32.J20 J32.J23 J32.J26 J32.J29 J32.J32 J32.J35 J32.J38 J32.J40 J32.K2 J32.K3 J32.K6 J32.K9 J32.K12 J32.K15 J32.K18 J32.K21 J32.K24 J32.K27 J32.K30 J32.K33 J32.K36 J32.K39 J37.3 L11.1 L12.1 L15.1 L16.1 L58.1 L59.1 L62.1 L63.1 Q21.2(E) Q22.2(E) Q23.2(E) R15.1 R16.1 R93.1 R96.1 R118.1 R119.1 R138.2 R139.2 R142.2 R143.2 R146.2 R147.2 R150.2 R151.2 R153.2 R154.2 R155.2 R157.2 R160.2 R162.2 R163.2 R164.2 R165.2 R167.2 R168.2 R173.2 R174.2 R176.2 R177.2 R179.2 R180.2 R182.2 R183.2 R185.2 R186.2 R187.2 R188.2 R190.2 R192.2 R193.2 R194.2 R195.1 R288.2 R289.2 R290.2 R291.2 R292.2 R293.2 R294.2 R340.1 R341.1 R345.1 R346.1 R367.2 T12.1(NC) T12.2(PRI/GND) T14.1(NC) T14.2(PRI/GND) T16.1(NC) T16.2(PRI/GND) T18.1(NC) T18.2(PRI/GND) T24.2(secondary_ct) T24.4(primary) U2.6(GND) U2.7(GND) U2.8(GND) U2.17(PWRPAD) U3.65(DAP) U31.3(A2) U31.4(VSS) Y1.3(GND) ; also on sheet 1 2 4 6 7 8 9 10 18 19 20 21
VDDA_1.8V: C183.1 C192.1 C196.1 C203.1 C211.1 C215.1 C441.1 C442.1 C457.1 C458.1 L27.2 L28.1 L29.1 L31.1 L33.2 L34.1 L35.2 L36.1 L37.1 L39.1 L41.2 L42.1 ; also on sheet 8 20
3P3V_FMC: J32.C39 J32.D36 J32.D38 J32.D40 PP30.1
3P3VAUX: C422.2 J32.D32 J37.4 PP31.1 U31.8(VCC)
ADC_ALT_SYNC_N: J32.H32 ; also on sheet 7
ADC_ALT_SYNC_P: J32.H31 ; also on sheet 7
ADC_SYNC_N: J32.G13 ; also on sheet 7
ADC_SYNC_P: J32.G12 ; also on sheet 7
C_IN1: J18.1(CENTER) R94.1 R96.2
C_IN2: J19.1(CENTER) R340.2 R342.1
CAR_SYSREF_M: R158.1 R162.1 U3.4(SDCLKOUT1n)
CAR_SYSREF_P: R156.1 R163.1 U3.3(SDCLKOUT1p)
CAR_SYSREFM: J32.G10 R158.2
CAR_SYSREFP: J32.G9 R156.2
CIN1: C155.2 L12.2 T12.3(PRI_DOT)
CIN1M: C147.1 ; also on sheet 4
CIN1P: C146.1 ; also on sheet 4
CIN2: C487.2 L59.2 T14.3(PRI_DOT)
CIN2M: C491.1 ; also on sheet 4
CIN2P: C490.1 ; also on sheet 4
CLK0_M2C_N: C423.2 J32.H5
CLK0_M2C_P: C424.2 J32.H4
CLK1_M2C_N: C425.2 J32.G3
CLK1_M2C_P: C426.2 J32.G2
CLK-IN: R159.1 R161.2 R165.1 T24.6(primary_dot)
CLK_LAO_0M: J32.G7 R191.2
CLK_LAO_0P: J32.G6 R189.2
CLKIN1_N: C230.2 C231.2 L43.2
CLKIN1_P: C227.2 L44.2
CLKIN1N: C239.2 L43.1 U3.35(CLKIN1n/FBCLKINn/FINn)
CLKIN1P: C238.2 L44.1 U3.34(CLKIN1p/FBCLKINp/FINp)
CLKINN: C231.1 R166.2 T24.3(secondary)
CLKINP: C227.1 R157.1 R159.2 R166.1 T24.1(secondary_dot)
CLKLA_0M: R191.1 R192.1 U3.63(DCLKOUT12n)
CLKLA_0P: R189.1 R190.1 U3.62(DCLKOUT12p)
CLKN: C228.2 ; also on sheet 4
CLKP: C229.2 ; also on sheet 4
CNTR_TAP_CHA: C187.1 C188.2 C190.1 C191.1 L29.2 T20.5(secondary_ct)
CNTR_TAP_CHB: C193.1 C194.1 C199.1 C200.2 L31.2 T21.5(secondary_ct)
CNTR_TAP_CHC: C206.1 C207.2 C209.1 C210.1 L37.2 T22.5(secondary_ct)
CNTR_TAP_CHD: C212.1 C213.1 C218.1 C219.2 L39.2 T23.5(secondary_ct)
CP1: C222.1 C223.1 R152.2 U3.32(CPOUT1) Y1.1(VC)
CP2: C225.1 C226.1 U3.46(CPOUT2)
D_IN1: J20.1(CENTER) R115.1 R118.2
D_IN2: J21.1(CENTER) R345.2 R347.1
DAC_ALT_SYNC_N: J32.F20 ; also on sheet 7
DAC_ALT_SYNC_P: J32.F19 ; also on sheet 7
DAC_SYNC_N: J32.F11 ; also on sheet 7
DAC_SYNC_P: J32.F10 ; also on sheet 7
DCLKOUT4N: C254.1 R188.1 U3.25(DCLKOUT4n)
DCLKOUT4P: C253.1 R187.1 U3.24(DCLKOUT4p)
DCLKOUT6N: C424.1 R289.1 U3.28(DCLKOUT6n)
DCLKOUT6P: C423.1 R290.1 U3.27(DCLKOUT6p)
DCLKOUT10N: C428.1 R293.1 U3.55(DCLKOUT10n)
DCLKOUT10P: C427.1 R294.1 U3.54(DCLKOUT10p)
DIN1: C148.2 L16.2 T16.3(PRI_DOT)
DIN1M: C154.1 ; also on sheet 4
DIN1P: C153.1 ; also on sheet 4
DIN2: C495.2 L63.2 T18.3(PRI_DOT)
DIN2M: C498.1 ; also on sheet 4
DIN2P: C499.1 ; also on sheet 4
DIV_IN: U2.2(CLK) ; also on sheet 4
DP0_C2M_N: J32.C3 ; also on sheet 5
DP0_C2M_P: J32.C2 ; also on sheet 5
DP0_M2C_N: J32.C7 ; also on sheet 5
DP0_M2C_P: J32.C6 ; also on sheet 5
DP1_C2M_N: J32.A23 ; also on sheet 5
DP1_C2M_P: J32.A22 ; also on sheet 5
DP1_M2C_N: J32.A3 ; also on sheet 5
DP1_M2C_P: J32.A2 ; also on sheet 5
DP2_C2M_N: J32.A27 ; also on sheet 5
DP2_C2M_P: J32.A26 ; also on sheet 5
DP2_M2C_N: J32.A7 ; also on sheet 5
DP2_M2C_P: J32.A6 ; also on sheet 5
DP3_C2M_N: J32.A31 ; also on sheet 5
DP3_C2M_P: J32.A30 ; also on sheet 5
DP3_M2C_N: J32.A11 ; also on sheet 5
DP3_M2C_P: J32.A10 ; also on sheet 5
DP4_C2M_N: J32.A35 ; also on sheet 5
DP4_C2M_P: J32.A34 ; also on sheet 5
DP4_M2C_N: J32.A15 ; also on sheet 5
DP4_M2C_P: J32.A14 ; also on sheet 5
DP5_C2M_N: J32.A39 ; also on sheet 5
DP5_C2M_P: J32.A38 ; also on sheet 5
DP5_M2C_N: J32.A19 ; also on sheet 5
DP5_M2C_P: J32.A18 ; also on sheet 5
DP6_C2M_N: J32.B37 ; also on sheet 5
DP6_C2M_P: J32.B36 ; also on sheet 5
DP6_M2C_N: J32.B17 ; also on sheet 5
DP6_M2C_P: J32.B16 ; also on sheet 5
DP7_C2M_N: J32.B33 ; also on sheet 5
DP7_C2M_P: J32.B32 ; also on sheet 5
DP7_M2C_N: J32.B13 ; also on sheet 5
DP7_M2C_P: J32.B12 ; also on sheet 5
EE_ADDR0_RX: J32.C34 U31.1(A0)
EE_ADDR1_RX: J32.D35 U31.2(A1)
FMC_FSPICLKA: J32.J6 ; also on sheet 7
FMC_FSPICLKB: J32.J7 ; also on sheet 7
FMC_FSPICLKC: J32.J9 ; also on sheet 7
FMC_FSPICLKD: J32.J10 ; also on sheet 7
FMC_FSPIDA: J32.J12 ; also on sheet 7
FMC_FSPIDB: J32.J13 ; also on sheet 7
FMC_FSPIDC: J32.J15 ; also on sheet 7
FMC_FSPIDD: J32.J16 ; also on sheet 7
FMC_LMK_CS: J32.H17 ; also on sheet 21
FMC_LMK_SCK: J32.G15 ; also on sheet 21
FMC_LMK_SDIO: J32.G16 ; also on sheet 21
FMC_LMK_SDO: J32.H16 ; also on sheet 21
FMC_RXADSA1PD: J32.K7 ; also on sheet 6
FMC_RXADSA2PD: J32.K8 ; also on sheet 6
FMC_RXADSAFAST: J32.G18 ; also on sheet 6
FMC_RXAPD2H: J32.K10 ; also on sheet 6
FMC_RXAPD2L: J32.K11 ; also on sheet 6
FMC_RXBDSA1PD: J32.K13 ; also on sheet 6
FMC_RXBDSA2PD: J32.K14 ; also on sheet 6
FMC_RXBDSAFAST: J32.G21 ; also on sheet 6
FMC_RXBPD2H: J32.J18 ; also on sheet 6
FMC_RXBPD2L: J32.J19 ; also on sheet 6
FMC_RXDSASW: J32.F13 ; also on sheet 6
FMC_SCL: J32.C30 J37.2 U31.6(SCL)
FMC_SDA: J32.C31 J37.1 U31.5(SDA)
FMC_SPIACLK: J32.D11 ; also on sheet 7
FMC_SPIASDIO: J32.D12 ; also on sheet 7
FMC_SPIASDO: J32.D26 ; also on sheet 7
FMC_SPIASEN: J32.D27 ; also on sheet 7
FMC_SPIBCLK: J32.E12 ; also on sheet 7
FMC_SPIBSDIO: J32.E13 ; also on sheet 7
FMC_SPIBSDO: J32.E15 ; also on sheet 7
FMC_SPIBSEN: J32.E16 ; also on sheet 7
FMC_TCK: J32.D29 ; also on sheet 7
FMC_TDI: J32.D30 ; also on sheet 7
FMC_TDO: J32.D31 ; also on sheet 7
FMC_TMS: J32.D33 ; also on sheet 7
FMC_TRSTB: J32.D34 ; also on sheet 7
FMC_TXDSASW: J32.F14 ; also on sheet 6
FMC_TXTDD1: J32.F16 ; also on sheet 6
FMC_TXTDD2: J32.F17 ; also on sheet 6
FPGA_CLK1_N: C241.2 J32.K5
FPGA_CLK1_P: C240.2 J32.K4
FPGA_CLK1N: C241.1 R177.1 U3.52(DCLKOUT8n)
FPGA_CLK1P: C240.1 R176.1 U3.51(DCLKOUT8p)
FPGA_CLK2_N: C250.2 J32.J3
FPGA_CLK2_P: C249.2 J32.J2
FPGA_CLK2N: C250.1 R182.1 U3.50(SDCLKOUT9n)
FPGA_CLK2P: C249.1 R183.1 U3.49(SDCLKOUT9p)
GBTCLK1_M2C_N: C428.2 J32.B21
GBTCLK1_M2C_P: C427.2 J32.B20
GTX_CLKM: C224.2 J32.D5
GTX_CLKP: C221.2 J32.D4
GTXCLKM: C224.1 R154.1 U3.2(DCLKOUT0n)
GTXCLKP: C221.1 R155.1 U3.1(DCLKOUT0p)
IOUTA: J22.1(CENTER) R136.1 R139.1
IOUTB: J23.1(CENTER) R140.1 R143.1
IOUTC: J24.1(CENTER) R144.1 R147.1
IOUTD: J25.1(CENTER) R148.1 R151.1
LMK LOCKED: D6.1(ANODE) R199.1
LMK_CLKIN: J26.1(CENTER) R161.1 R164.1
LMK_CS: U3.18(\\~{CS}) ; also on sheet 21
LMK_SCK: U3.19(SCK) ; also on sheet 21
LMK_SDIO: U3.20(SDIO) ; also on sheet 21
LMK_SDO: R195.2 U3.5(RESET) ; also on sheet 21
NB7_RESET: R205.2 U2.15(R)
OSCINN: C252.2 C255.2 U3.44(OSCINn)
OSCINP: C245.2 C247.2 U3.43(OSCINp)
OSCP: C244.2 C245.1 R175.2 R180.1
PG_C2M: J32.D1 R287.1
PG_M2C: J32.F1 R286.2
PLL2 LOCKED: D7.1(ANODE) R200.1
PRESENT: J32.H2 R288.1
SDCLKOUT5N: C257.1 R194.1 U3.23(SDCLKOUT5n)
SDCLKOUT5P: C256.1 R193.1 U3.22(SDCLKOUT5p)
SDCLKOUT7N: C426.1 R291.1 U3.30(SDCLKOUT7n)
SDCLKOUT7P: C425.1 R292.1 U3.29(SDCLKOUT7p)
STAT 0: D4.1(ANODE) R197.1
STAT 1: D5.1(ANODE) R198.1
SYNC: R196.2 U3.6(SYNC)
syncb0cmos: J32.E6 ; also on sheet 7
syncb1cmos: J32.E7 ; also on sheet 7
syncb2cmos: J32.E9 ; also on sheet 7
syncb3cmos: J32.E10 ; also on sheet 7
SYSREF+: R172.1 R174.1 U3.14(SDCLKOUT3n)
SYSREF-: R169.1 R173.1 U3.13(SDCLKOUT3p)
SYSREFN: R15.2 R169.2 ; also on sheet 4
SYSREFP: R16.2 R172.2 ; also on sheet 4
TXAM: L27.1 R137.2 T20.4(secondary_dot) ; also on sheet 4
TXAP: L28.2 R137.1 T20.6(secondary) ; also on sheet 4
TXBM: L34.2 R141.1 T21.6(secondary) ; also on sheet 4
TXBP: L33.1 R141.2 T21.4(secondary_dot) ; also on sheet 4
TXCM: L35.1 R145.2 T22.4(secondary_dot) ; also on sheet 4
TXCP: L36.2 R145.1 T22.6(secondary) ; also on sheet 4
TXDM: L42.2 R149.1 T23.6(secondary) ; also on sheet 4
TXDP: L41.1 R149.2 T23.4(secondary_dot) ; also on sheet 4
VADJ: J32.E39 J32.F40 J32.G39 J32.H40 R286.1
VIO_B_M2C: J32.J39 J32.K40 TP3.1(TP)
VREF_A_M2C: J32.H1 TP4.1(TP)
VREF_B_M2C: J32.K1 TP5.1(TP)
Y2_N: R184.1 R185.1 Y1.4(OUT_N)
Y2_P: R178.1 R179.1 Y1.5(OUT_P)
YO2_N: C251.1 R184.2
YO2_P: C244.1 R178.2
N17906763: J31.1(CENTER) R196.1
N18199775: C251.2 C252.1 R181.2 R186.1
N18276385: C238.1 R171.2 U2.11(Q)
N18284119: C239.1 R170.2 U2.10(~{Q})
N18332593: U2.1(VTCLK) U2.4(~{VTCLK}) U2.5(VREFAC)
N18476239: SHUNT1.1 Y1.6(VDD)
N18864728: Q22.1(B) R204.2
N18864745: J32.C18 R202.1
N18864749: Q23.1(B) R206.2
N18864761: J32.D18 R206.1
N18864763: J32.D17 R204.1
N18864798: Q22.3(C) R203.2
N18864814: Q21.1(B) R202.2
N18865554: D9.2(CATHODE) R203.1
N18865572: D8.2(CATHODE) R201.1
N18865624: D10.2(CATHODE) R207.1
N18865630: J32.H19 R205.1
N18883805: C186.1 C187.2 C189.2 T20.2(primary)
N18883857: C184.2 R136.2 R138.1
N18883928: C195.2 R140.2 R142.1
N18883944: C198.2 C199.2 C201.2 T21.2(primary)
N18884373: C184.1 C185.2 T20.3(primary_dot)
N18884375: C195.1 C197.2 T21.3(primary_dot)
N18885333: C205.2 C206.2 C208.2 T22.2(primary)
N18885345: C202.2 R144.2 R146.1
N18885353: C214.2 R148.2 R150.1
N18885357: C217.2 C218.2 C220.2 T23.2(primary)
N18885439: C202.1 C204.2 T22.3(primary_dot)
N18885440: C214.1 C216.2 T23.3(primary_dot)
N19080738: C242.2 C243.2 C246.2 C248.2 FB1.1 SHUNT1.2
N19081029: R366.2 R367.1 Y1.2(NC)
N19083254: R199.2 U3.31(STATUS_LD1)
N19083268: R200.2 U3.48(STATUS_LD2)
N19083286: R198.2 U3.59(CLKin_SEL1)
N19083328: R197.2 U3.58(CLKin_SEL0)
N19083344: C267.1 U3.12(LDObyp2)
N19083346: C268.1 U3.11(LDObyp1)
N19083364: C258.2 C259.2 C260.2 FB2.2 U3.10(VCC1_VCO) U3.33(VCC5_DIG) U3.36(VCC6_PLL1)
N19083444: FB7.2 U3.39(VCC7_OSCout)
N19083446: FB9.2 U3.45(VCC9_CP2)
N19083508: C264.2 C265.2 C266.2 FB6.2 FB7.1 FB8.1 FB9.1 U3.47(VCC10_PLL2)
N19083566: C262.2 FB3.2 U3.21(VCC3_SYSREF)
N19083568: C261.2 FB5.2 U3.17(VCC2_CG1)
N19083616: C270.2 FB11.2 U3.64(VCC12_CG0)
N19083618: C269.2 FB10.2 U3.53(VCC11_CG3)
N19083707: C263.2 FB4.2 U3.26(VCC4_CG2)
N19086842: C229.1 R168.1 U3.16(DCLKOUT2n)
N19086844: C228.1 R167.1 U3.15(DCLKOUT2p)
N19189047: C253.2 J27.1(CENTER)
N19189049: C254.2 J28.1(CENTER)
N19234861: FB8.2 U3.42(VCC8_OSCin)
N19270100: C256.2 J29.1(CENTER)
N19270102: C257.2 J30.1(CENTER)
N19667706: D14.1(ANODE) R287.2
N20138109: C157.1 R358.2 T13.6(PRI_DOT)
N20138119: C157.2 C159.2 L13.2
N20138121: C158.2 C160.2 L13.1
N20138123: C160.1 L14.1 R97.2
N20138125: C159.1 L14.2 R95.2
N20138185: C146.2 R95.1
N20138187: C147.2 R97.1
N20138199: C155.1 L11.2 R93.2 R94.2
N20138318: C158.1 R359.2 T13.4(PRI)
N20138362: C161.2 T13.2(NC)
N20138813: C149.1 R362.2 T17.6(PRI_DOT)
N20138823: C149.2 C151.2 L17.2
N20138825: C150.2 C152.2 L17.1
N20138827: C152.1 L18.1 R116.2
N20138829: C151.1 L18.2 R114.2
N20138855: R362.1 T16.5(SEC) T17.1(SEC_DOT)
N20138857: R363.1 T16.4(SEC_DOT) T17.3(SEC)
N20138889: C153.2 R114.1
N20138891: C154.2 R116.1
N20138903: C148.1 L15.2 R115.2 R119.2
N20139022: C150.1 R363.2 T17.4(PRI)
N20148716: R359.1 T12.4(SEC_DOT) T13.3(SEC)
N20186999: R358.1 T12.5(SEC) T13.1(SEC_DOT)
N20188389: C156.2 T17.2(NC)
N20222985: R360.1 T14.5(SEC) T15.1(SEC_DOT)
N20222995: R361.1 T14.4(SEC_DOT) T15.3(SEC)
N20223001: C485.1 R360.2 T15.6(PRI_DOT)
N20223005: C485.2 C488.2 L60.2
N20223007: C486.2 C489.2 L60.1
N20223009: C489.1 L61.1 R344.2
N20223011: C488.1 L61.2 R343.2
N20223065: C490.2 R343.1
N20223067: C491.2 R344.1
N20223080: C487.1 L58.2 R341.2 R342.2
N20223194: C486.1 R361.2 T15.4(PRI)
N20223236: C492.2 T15.2(NC)
N20223675: R364.1 T18.5(SEC) T19.1(SEC_DOT)
N20223681: C500.2 T19.2(NC)
N20223685: C493.1 R364.2 T19.6(PRI_DOT)
N20223687: C493.2 C496.2 L64.2
N20223689: C494.2 C497.2 L64.1
N20223691: C497.1 L65.1 R349.2
N20223693: C496.1 L65.2 R348.2
N20223728: R365.1 T18.4(SEC_DOT) T19.3(SEC)
N20223751: C499.2 R348.1
N20223753: C498.2 R349.1
N20223766: C495.1 L62.2 R346.2 R347.2
N20223882: C494.1 R365.2 T19.4(PRI)
N20528266: Q23.3(C) R207.2
N20528267: Q21.3(C) R201.2
N20529761: C225.2 R160.1
N20529762: C222.2 R153.1

Not connected (* = marked no-connect by the designer): J32 B1 B4 B5 B8 B9 B24 B25 B28 B29 B40 C10* C11* C14 C15 C19* C22* C23* C26* C27* D8 D9 D14 D15 D20 D21 D23 D24 E2 E3 E18 E19 E21 E22 E24 E25 E27 E28 E30 E31 E33 E34 E36 E37 F2 F4 F5 F7 F8 F22 F23 F25 F26 F28 F29 F31 F32 F34 F35 F37 F38 G19 G22 G24 G25 G27 G28 G30 G31 G33 G34 G36 G37 H7 H8 H10 H11 H13 H14 H20 H22 H23 H25 H26 H28 H29 H34 H35 H37 H38 J21 J22 J24 J25 J27 J28 J30 J31 J33 J34 J36 J37 K16 K17 K19 K20 K22 K23 K25 K26 K28 K29 K31 K32 K34 K35 K37 K38; T12 6(NC1); T14 6(NC1); T16 6(NC1); T18 6(NC1)*; T20 1(notused)*; T21 1(notused)*; T22 1(notused)*; T23 1(notused)*; U2 3(~{CLK})*; U3 7(NC1)* 8(NC2)* 9(NC3)* 37(CLKIN0p)* 38(CLKIN0n)* 40(OSCOUTp)* 41(OSCOUTn)* 56(SDCLKOUT11p)* 57(SDCLKOUT11n)* 60(SDCLKOUT13p)* 61(SDCLKOUT13n)*

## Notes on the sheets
sheet 11
- Shared
  Pad
- Shared Pad
- Shared Pad
- Shared Pad
- Shared Pad
- Shared Pad
- Shared Pad
- Shared Pad
- Shared Pad
- Shared Pad
- Shared Pad
- Shared Pad
- Shared Pad
- Shared Pad
- Shared Pad
- Shared Pad
sheet 12
- Place the parts
- Place the parts
- and route on
- and route on
- the solder side.
- the top side.
sheet 13
- Place the parts
- Place the parts
- and route on
- and route on
- the top side.
- the solder side.
sheet 14
- TSW JESD Interface
  reference clock w/
  LVDS levels
- Place near Vc pin of Y1
  R152 and C223 form voltage divider
  set the center frequency voltage for PLL2 reference
- MATCHED LENGTH
- Place close to LMK
- R159 TO SHARE PADS W/ T24
- Place close to LMK
- Shared Pad
- MATCHED LENGTH
- JESD SYSREF
- MATCHED LENGTH
- Place close to LMK
- Y1 CMOS version OUTPUT on PIN 4
- JESD CORECLOCK
sheet 16
- 12500 TI Boulevard. Dallas, Texas 75243
